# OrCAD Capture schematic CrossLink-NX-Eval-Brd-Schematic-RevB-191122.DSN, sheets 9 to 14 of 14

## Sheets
9 Configuration And ADC: size B; title: Configuration and ADC
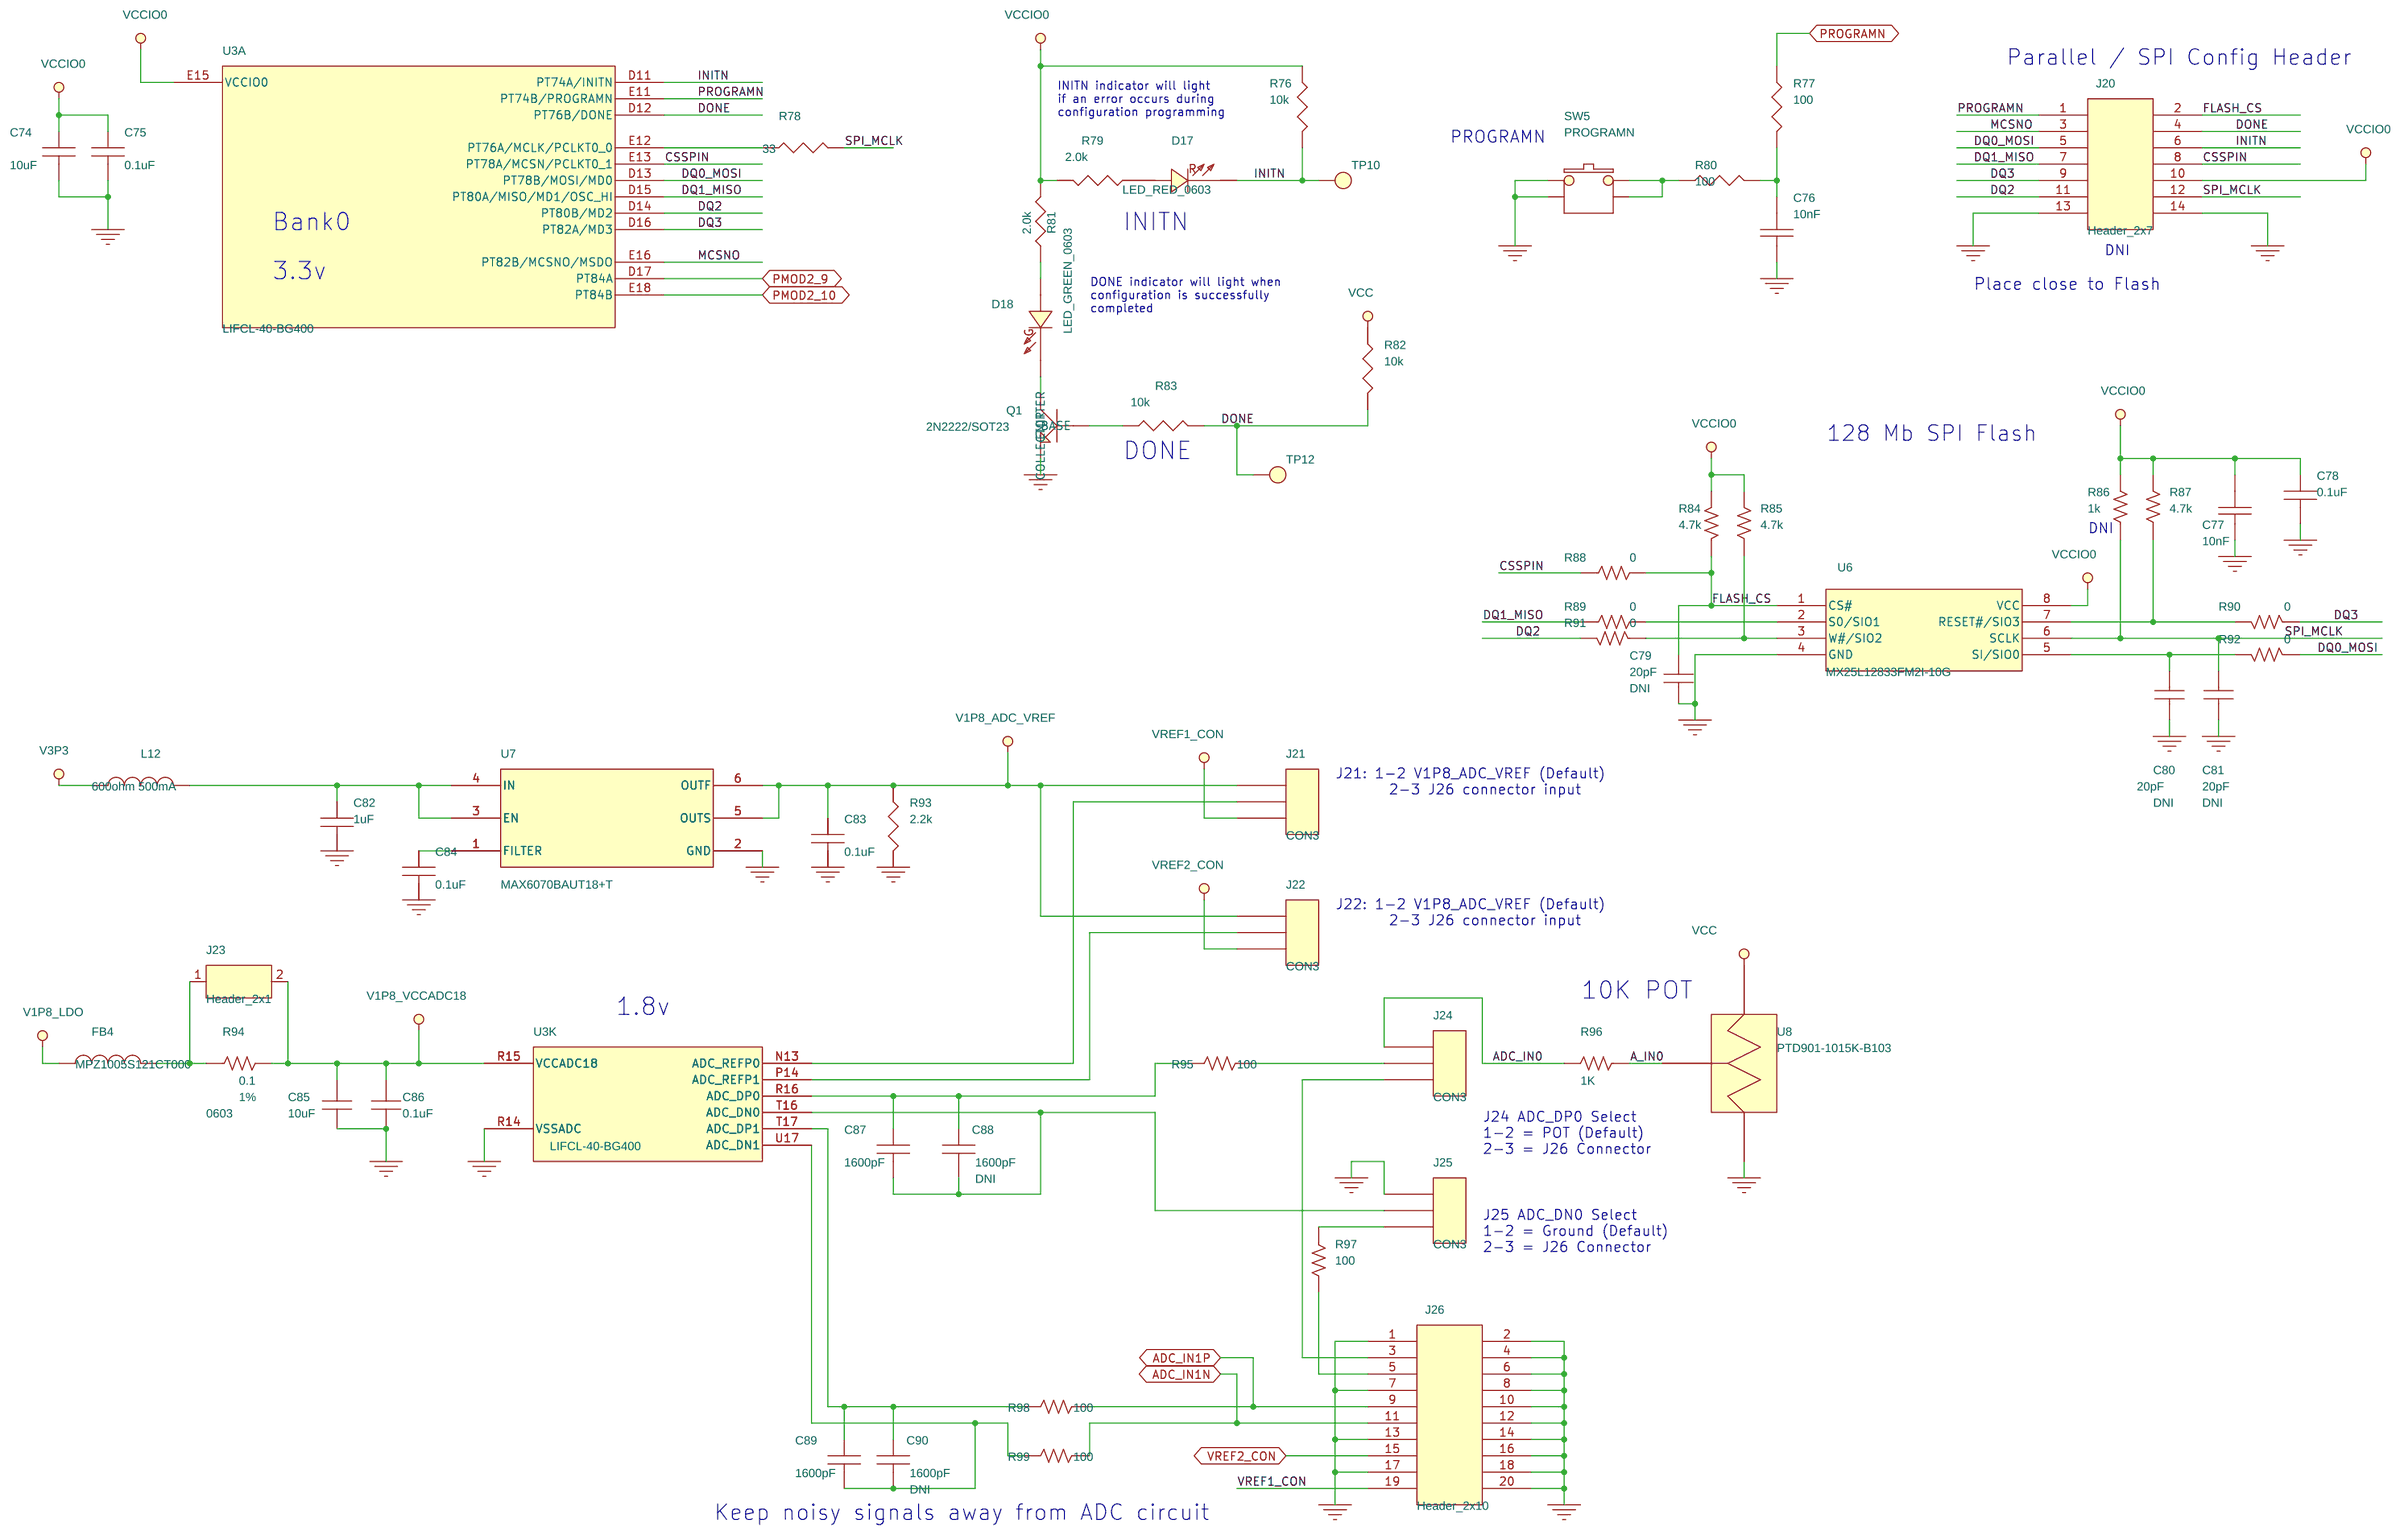
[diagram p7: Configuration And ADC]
10 FMC-LPC: size B; title: FMC-LPC
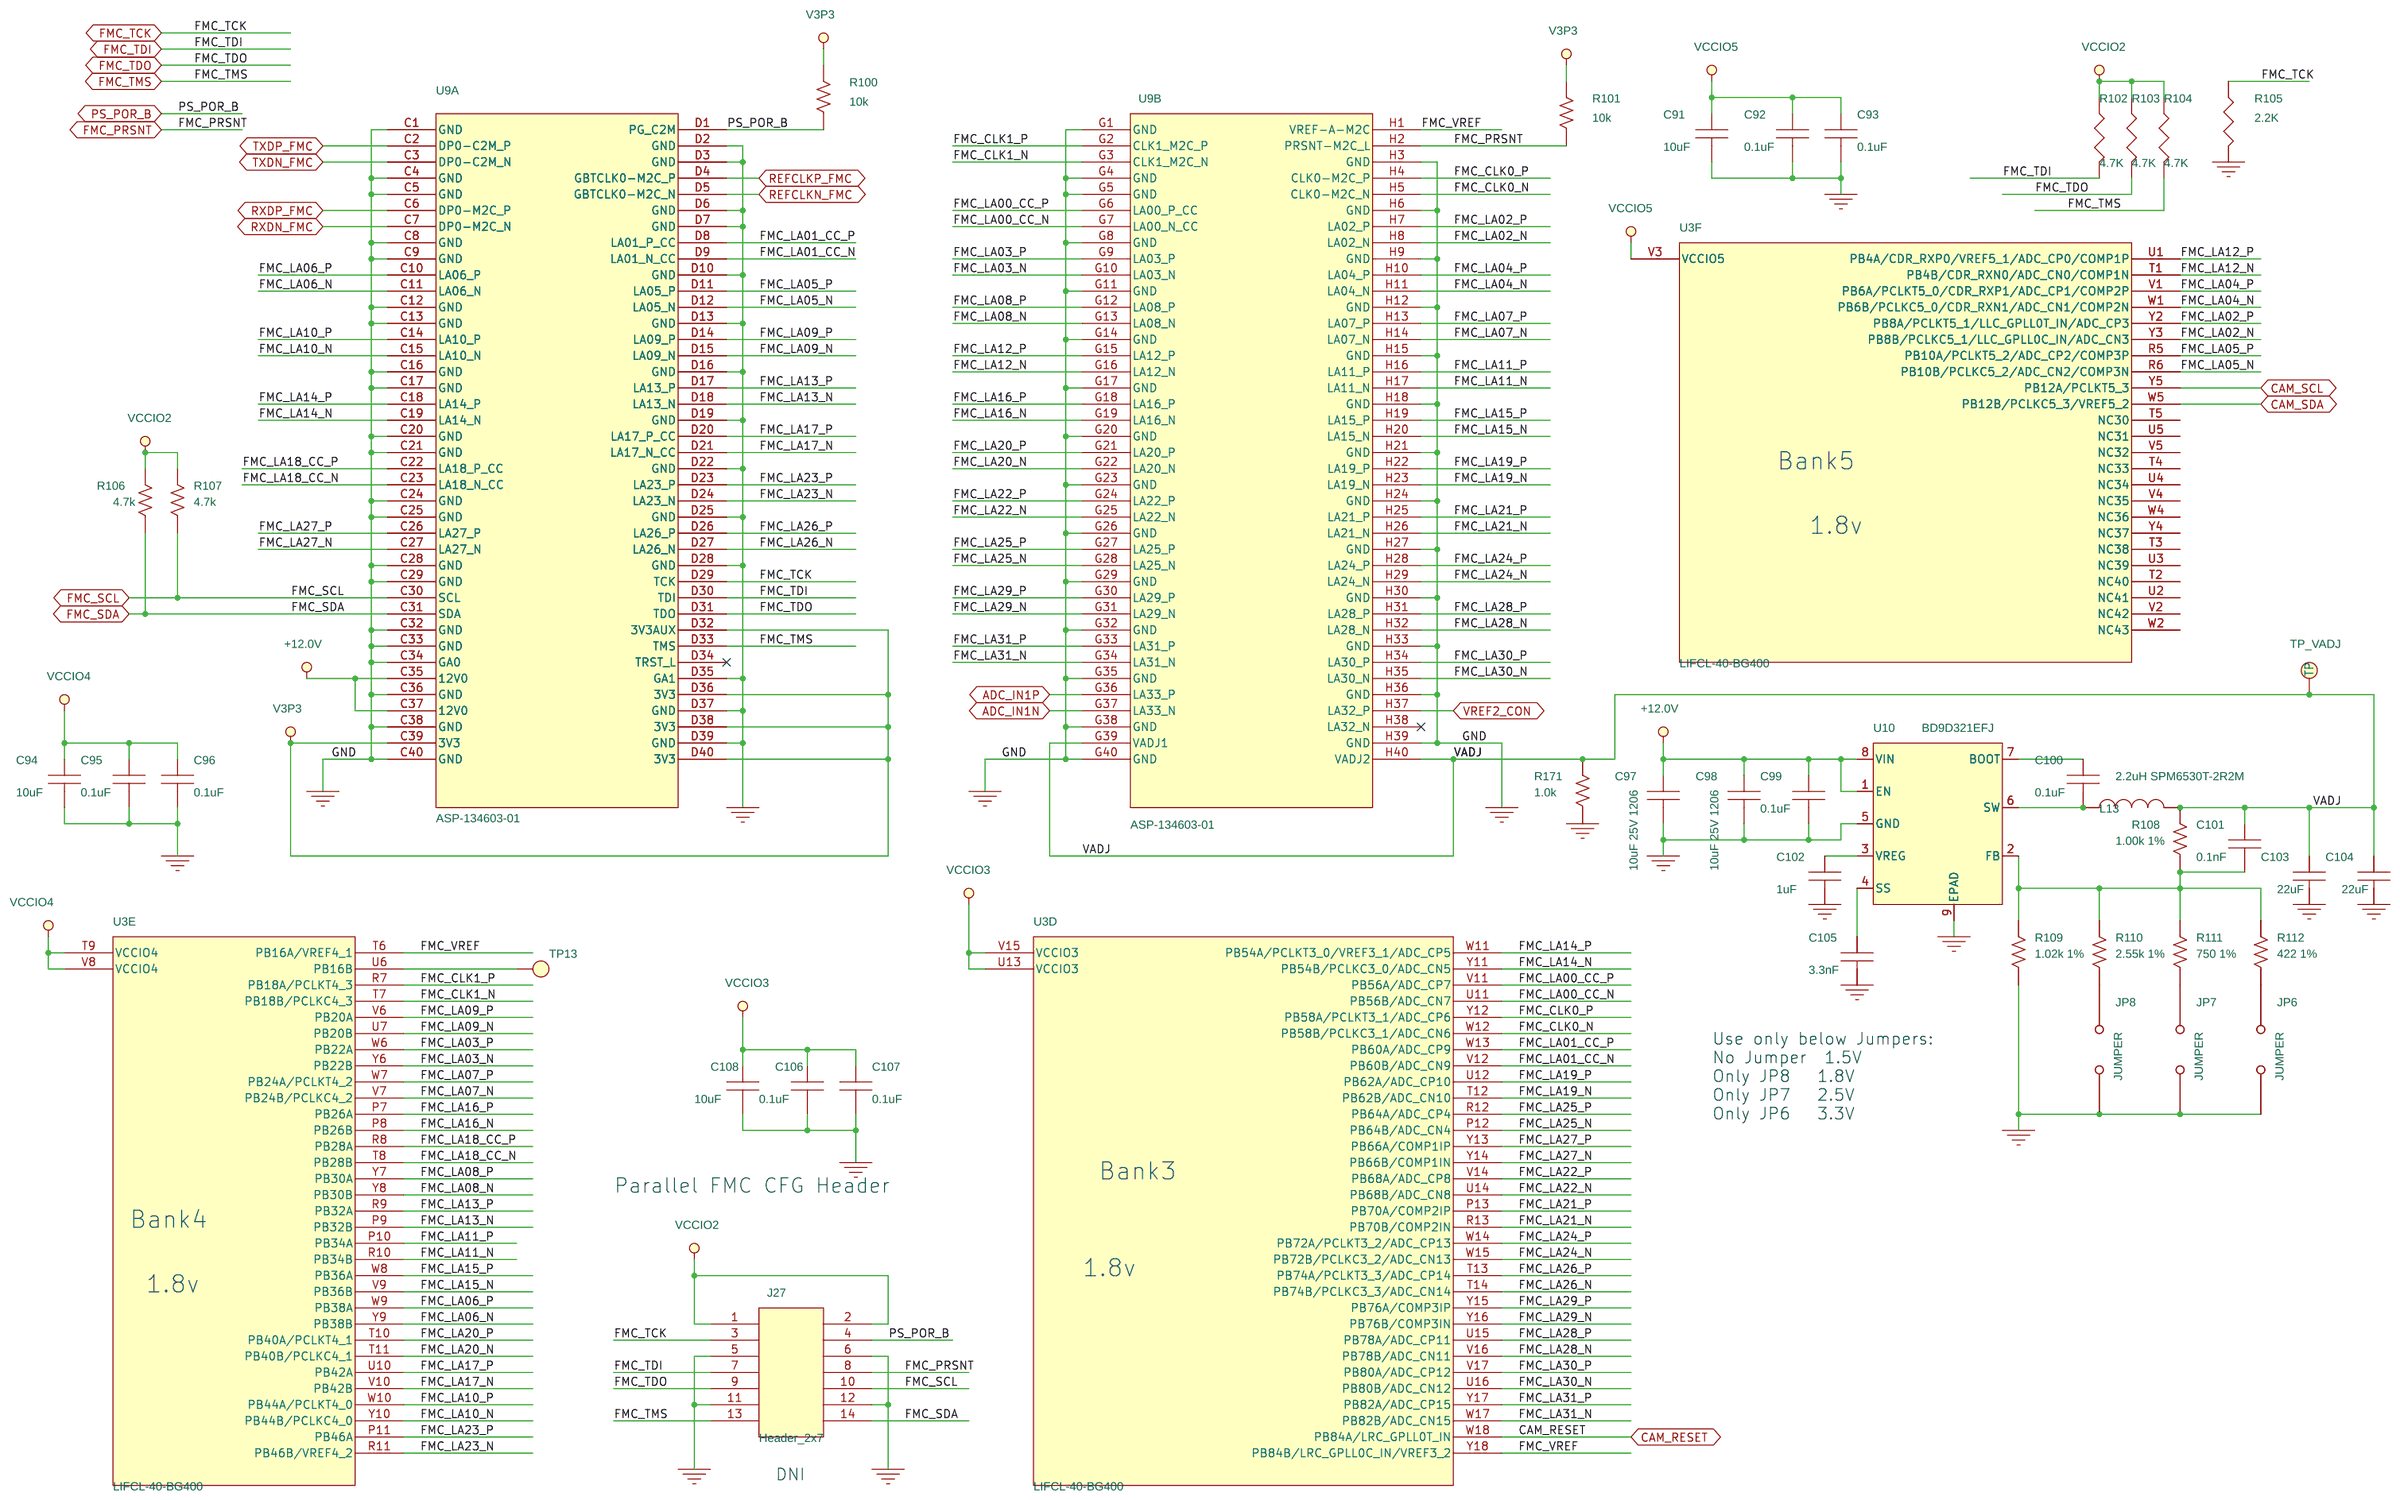
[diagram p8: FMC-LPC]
11 Power CSI and Bank Power: size B; title: Power CSI and Banks
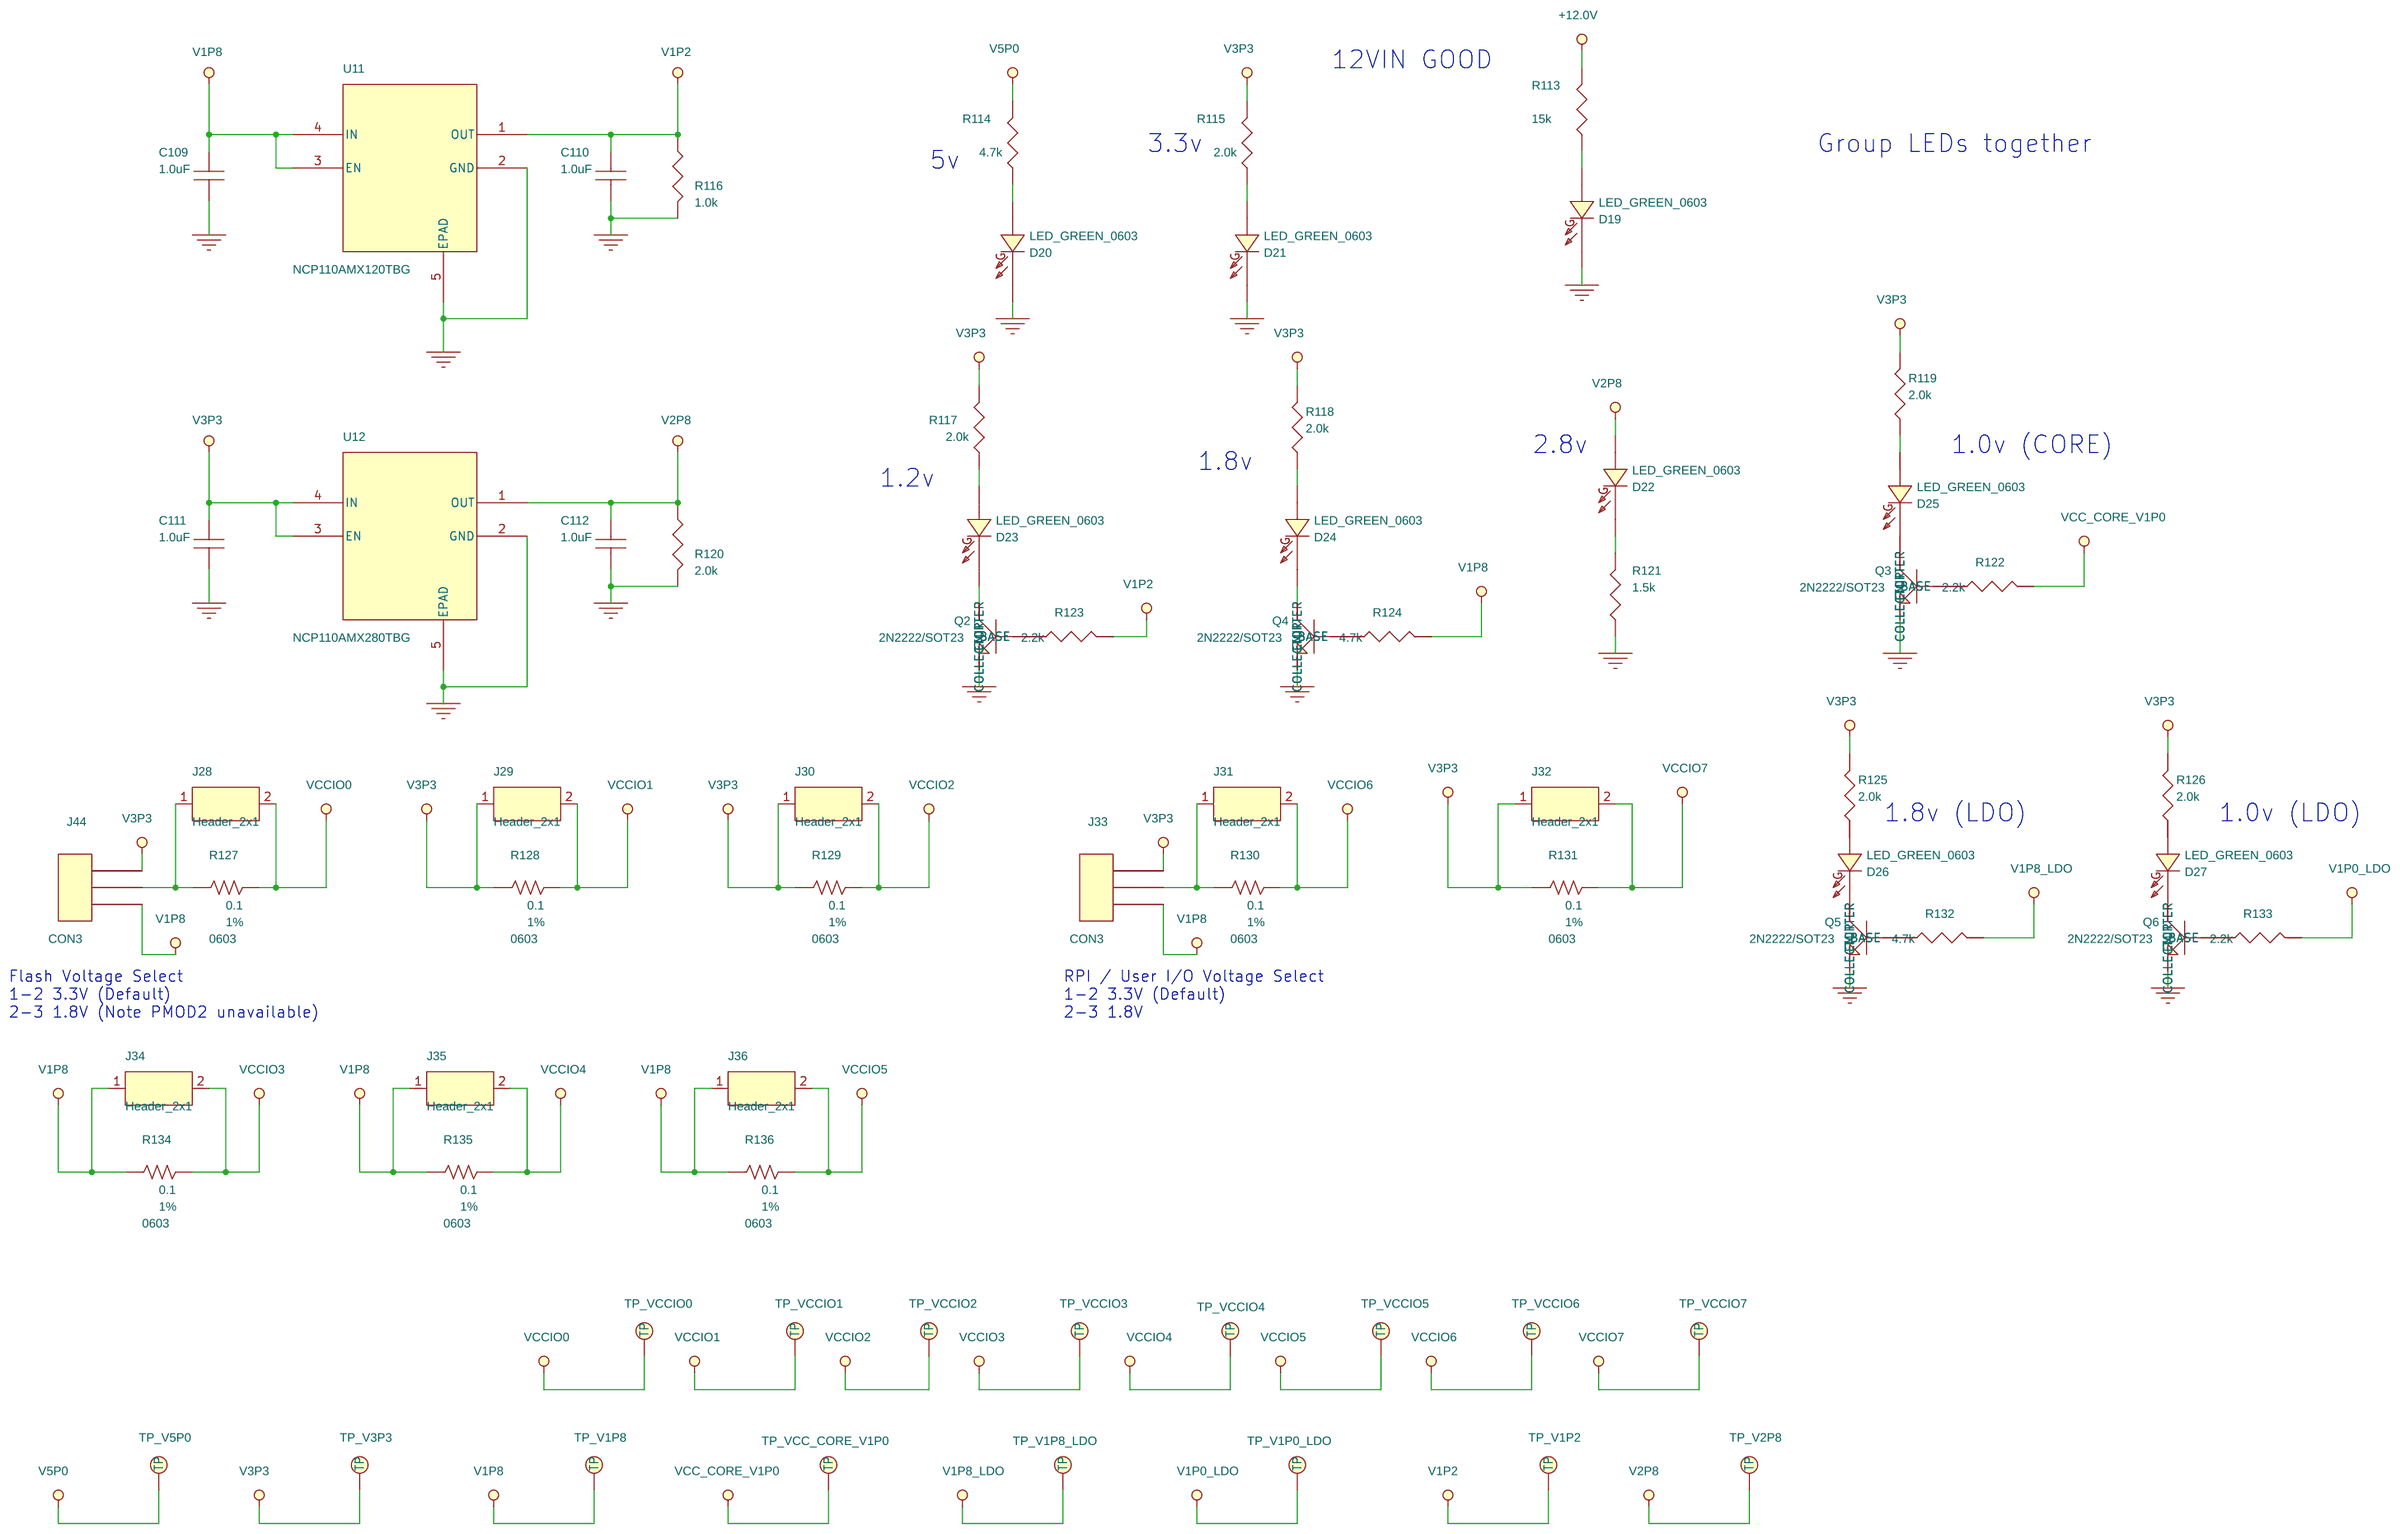
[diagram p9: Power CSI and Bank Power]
12 Power Decoupling: size B; title: Power Decoupling
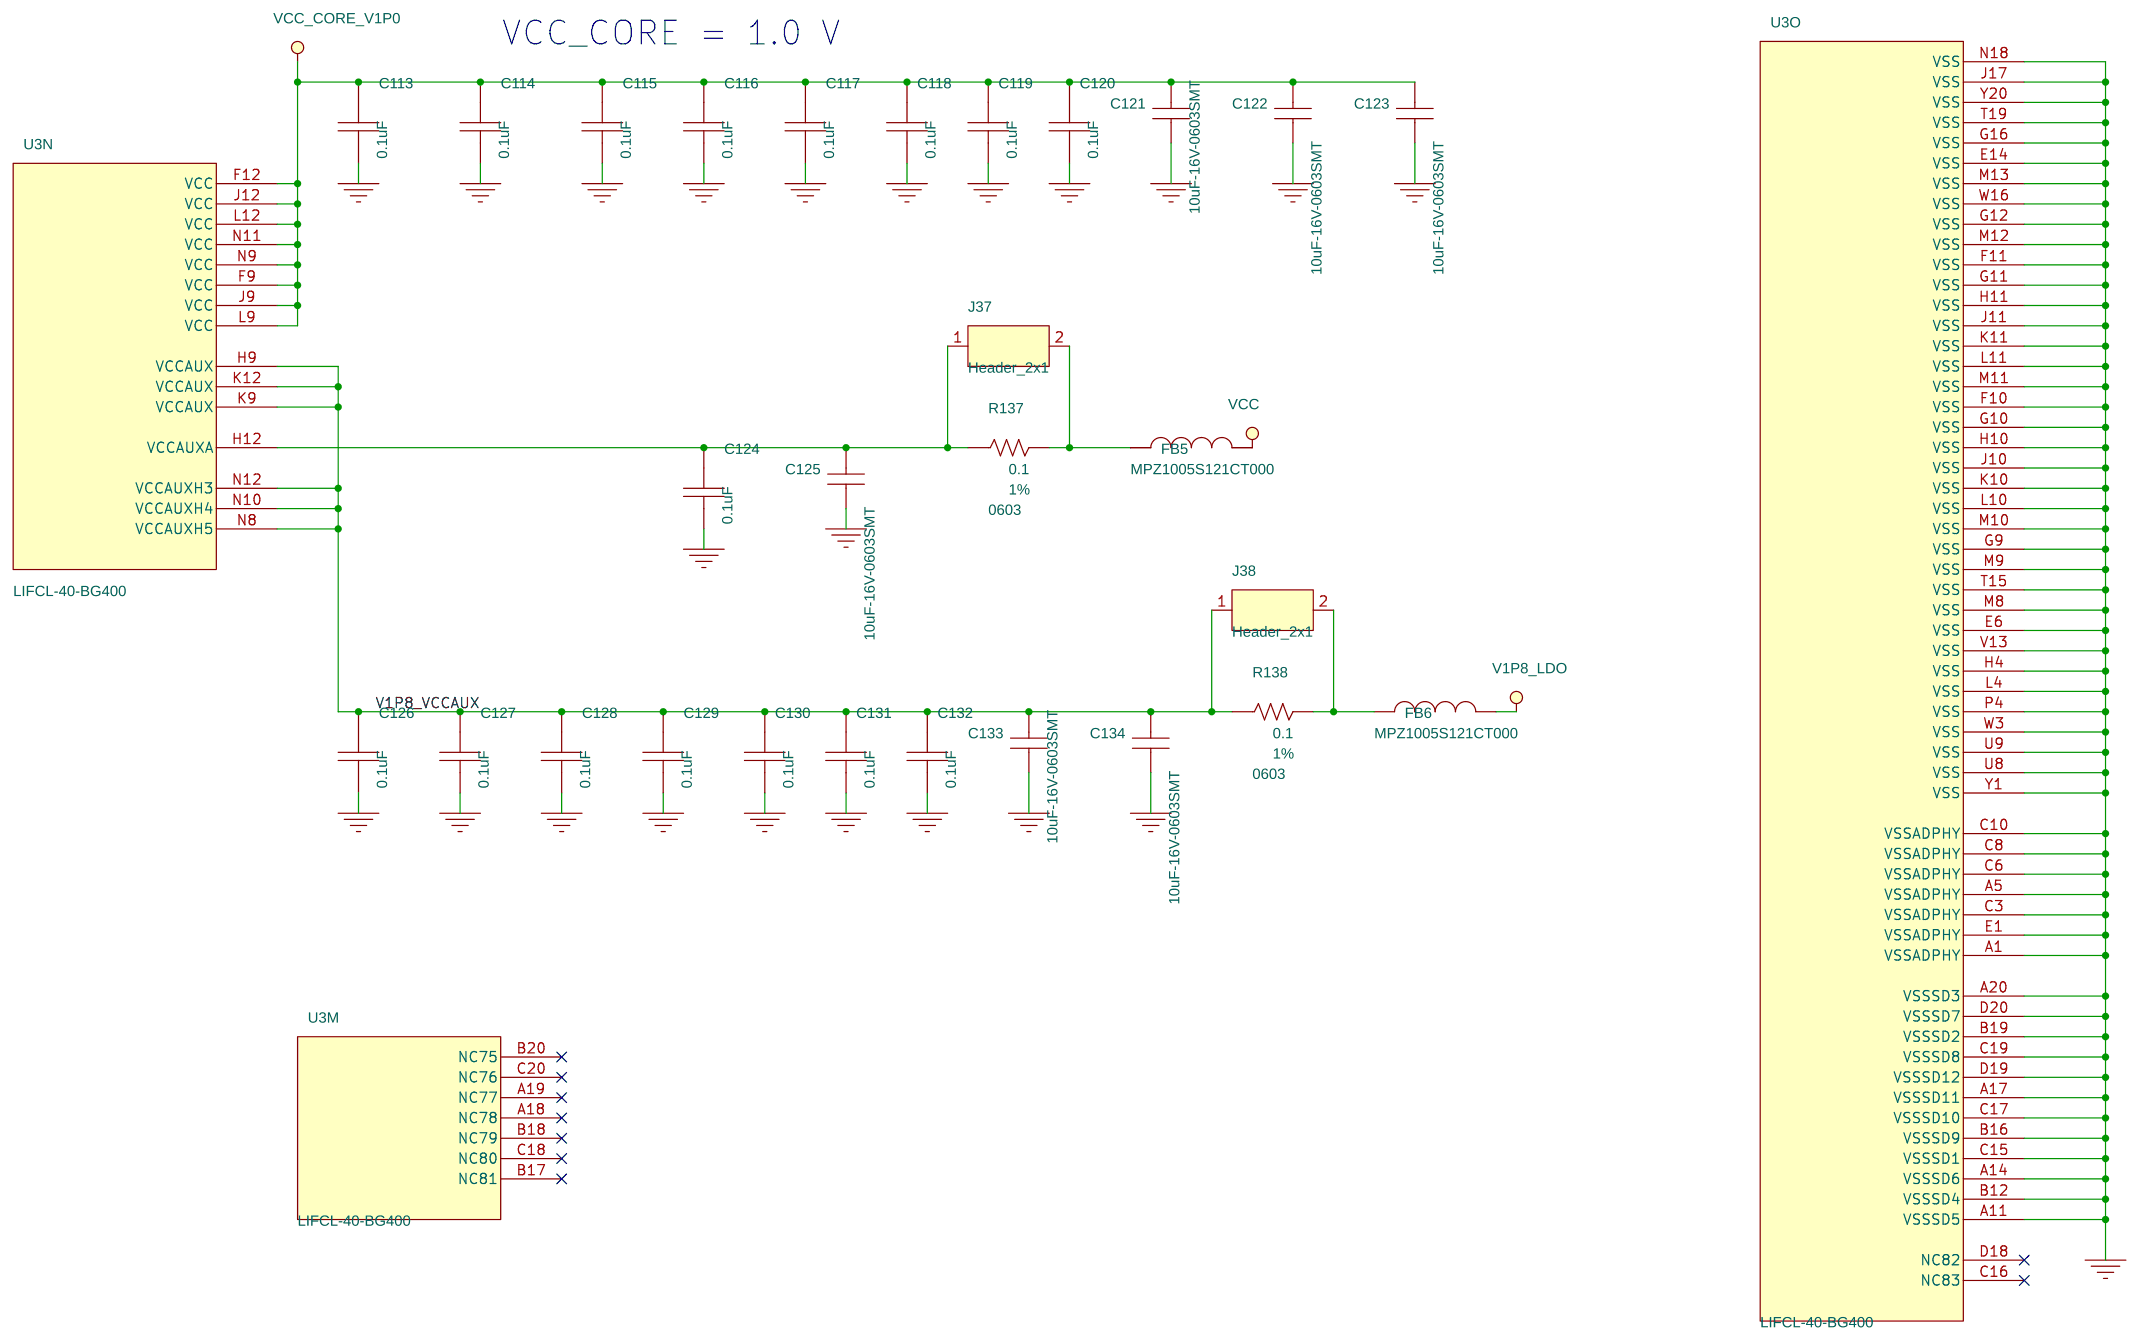
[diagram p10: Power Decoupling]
13 Power Regulators: size B; title: Power Regulators
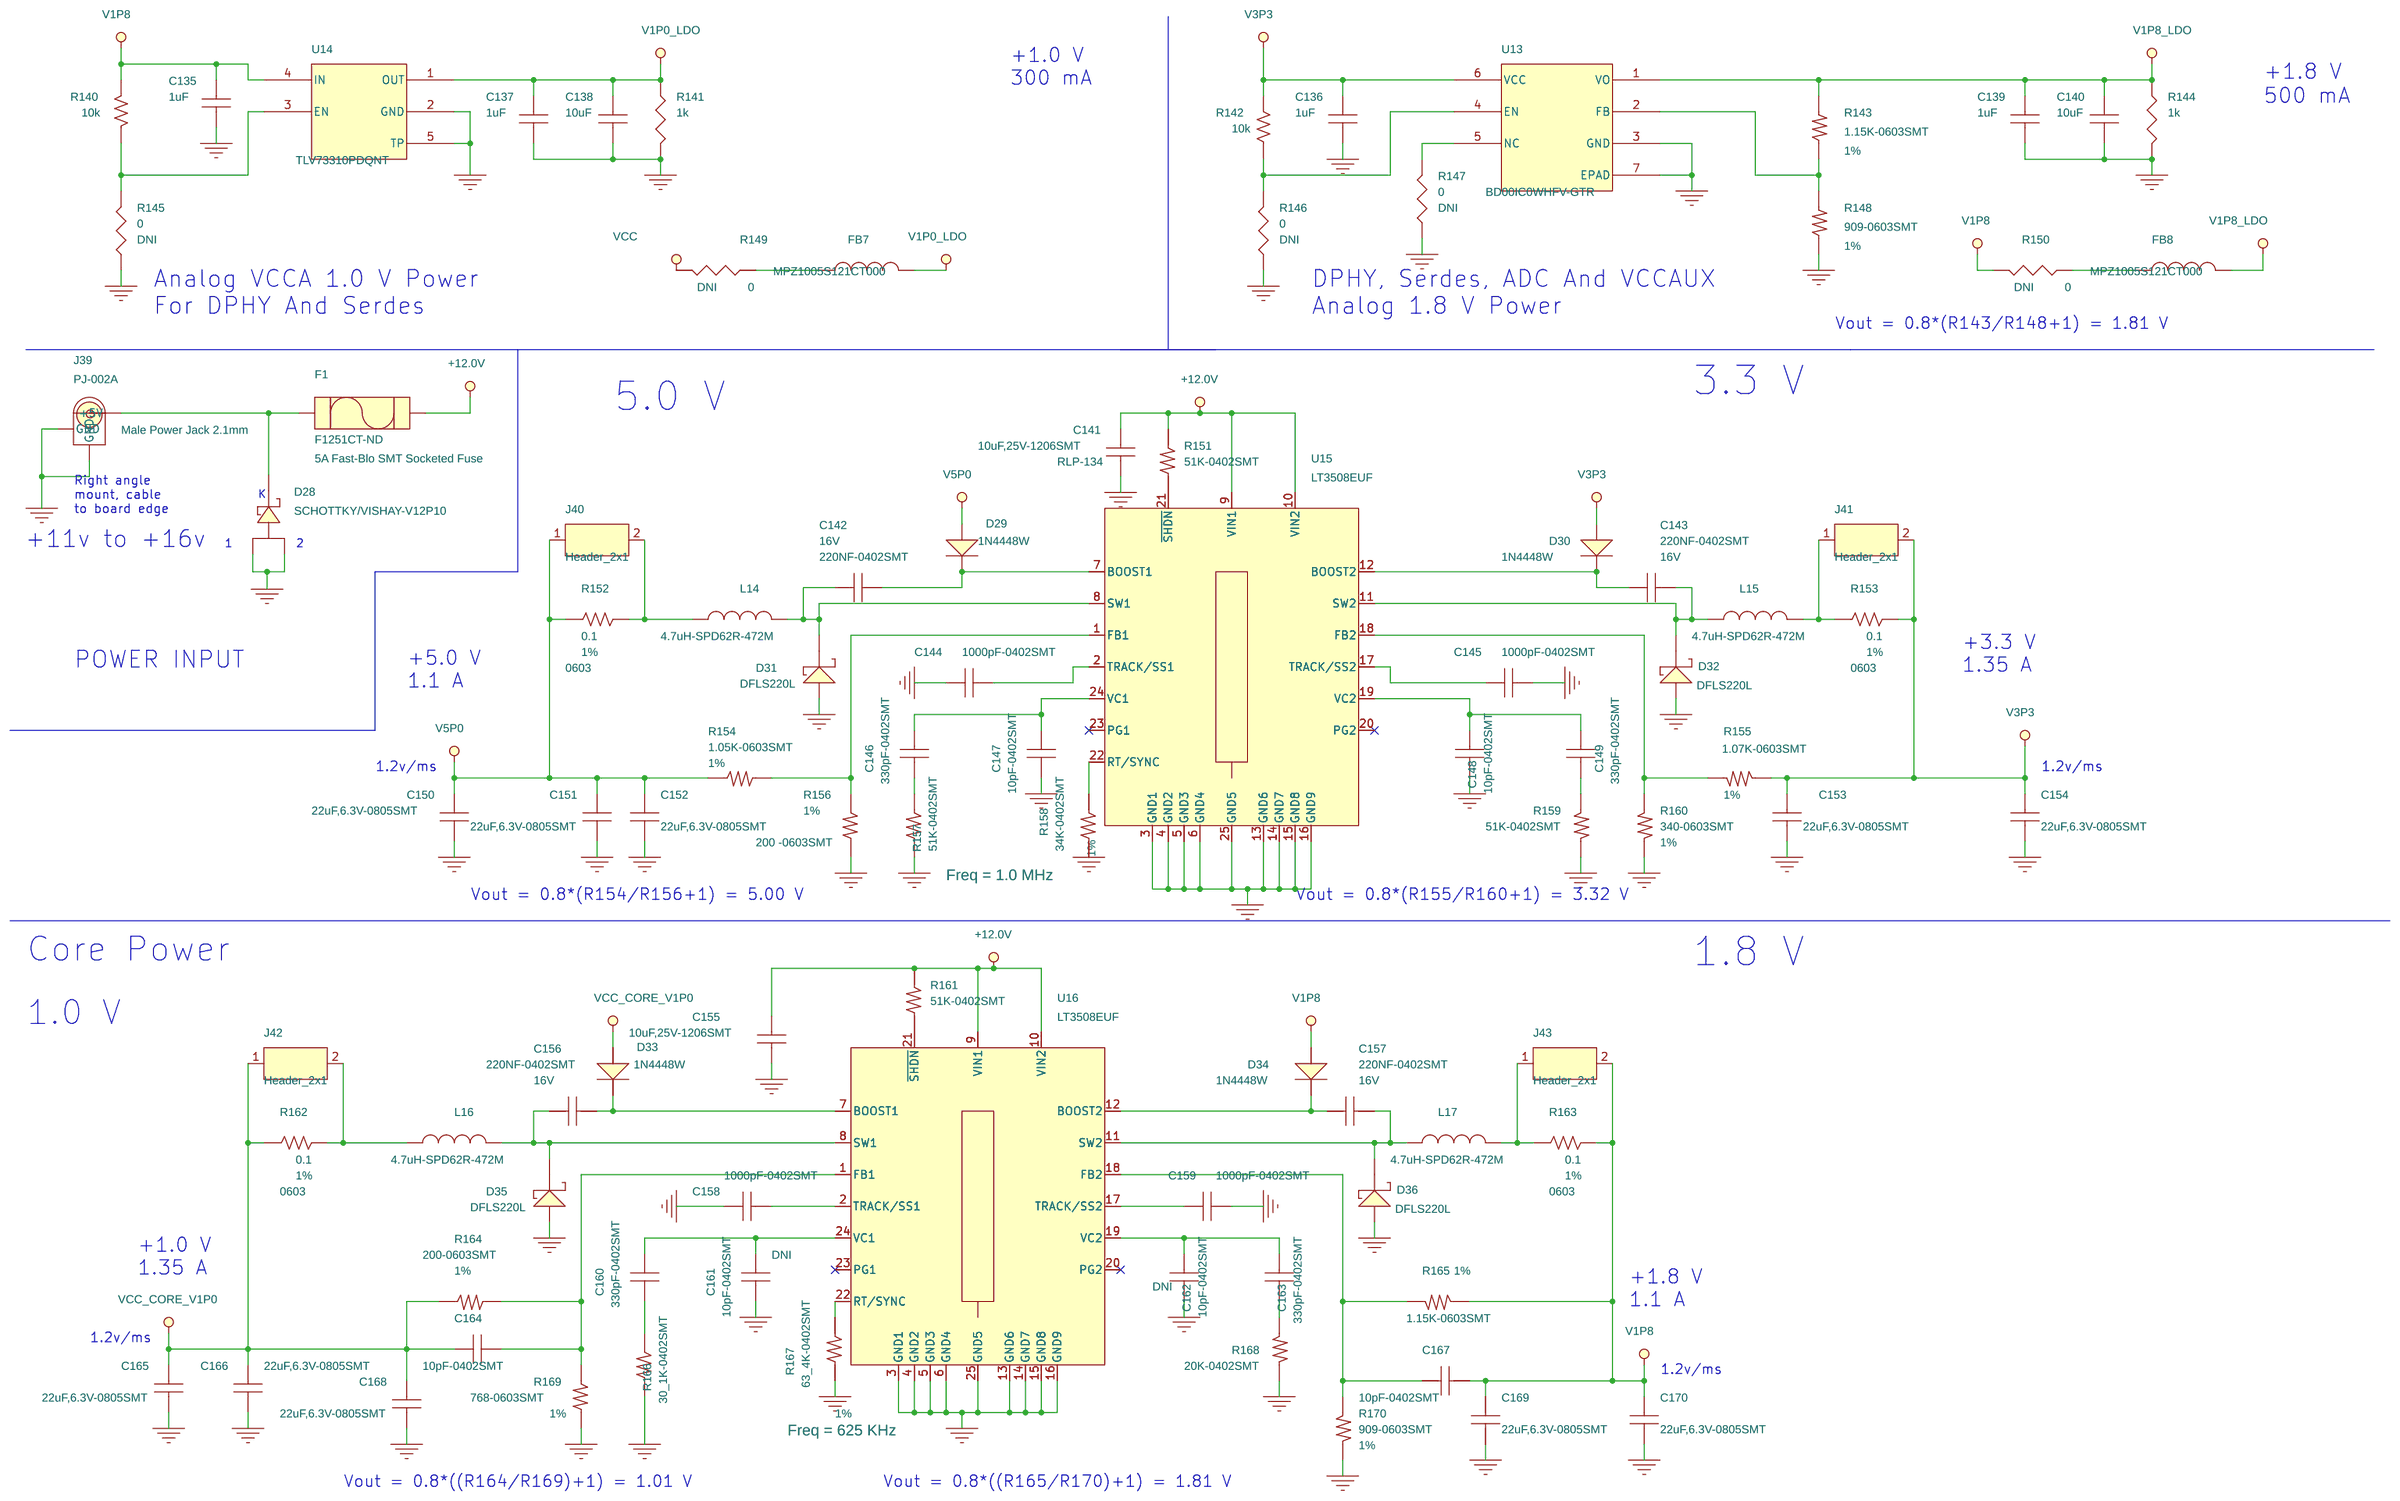
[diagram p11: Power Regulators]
14 Power Diagram: title: Power Block Diagram

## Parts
sheet Configuration And ADC
C74  10uF  [C0603]
C75  0.1uF  [C0201]
C76  10nF  [RLP-130-A]
C77  10nF  [RLP-130-A]
C78  0.1uF  [C0201]
C79  20pF  [RLP-132]
C80  20pF  [RLP-132]
C81  20pF  [RLP-132]
C82  1uF  [C0603]
C83  0.1uF  [C0201]
C84  0.1uF  [C0201]
C85  10uF  [C0402]
C86  0.1uF  [C0201]
C87  1600pF  [C0805]
C88  1600pF  [C0805]
C89  1600pF  [C0805]
C90  1600pF  [C0805]
D17  LED_RED_0603  [APT1608]
D18  LED_GREEN_0603  [APT1608]
FB4  MPZ1005S121CT000  [FB0402]
J20  Header_2x7  [Header_2x7]
J21  CON3  [CON3]
J22  CON3  [CON3]
J23  Header_2x1  [Header_2x1]
J24  CON3  [CON3]
J25  CON3  [CON3]
J26  Header_2x10  [Header_2x10]
L12  600ohm 500mA  [fb0603]
Q1  2N2222/SOT23  [MMBT2222ALT-1]
R76  10k  [R0402]
R77  100  [R0402]
R78  33  [R0402]
R79  2.0k  [R0402]
R80  100  [R0402]
R81  2.0k  [R0402]
R82  10k  [R0402]
R83  10k  [R0402]
R84  4.7k  [R0402]
R85  4.7k  [R0402]
R86  1k  [R0402]
R87  4.7k  [R0402]
R88  0  [R0402]
R89  0  [R0402]
R90  0  [R0402]
R91  0  [R0402]
R92  0  [R0402]
R93  2.2k  [R0402]
R94  0.1  [0603]
R95  100  [R0805]
R96  1K  [R0805]
R97  100  [R0805]
R98  100  [R0805]
R99  100  [R0805]
SW5  PROGRAMN  [4psmd_switch]
TP10  TestPoint  [TP50]
TP12  TestPoint  [TP50]
U6  MX25L12833FM2I-10G  [SO8_MX25L12833FM2I10G]
U7  MAX6070BAUT18+T  [SOT23-6_MAX6070]
U8  PTD901-1015K-B103  [PTD901_1015K_B103]
sheet FMC-LPC
C91  10uF  [C0603]
C92  0.1uF  [C0201]
C93  0.1uF  [C0201]
C94  10uF  [C0603]
C95  0.1uF  [C0201]
C96  0.1uF  [C0201]
C97  10uF 25V 1206  [C1206]
C98  10uF 25V 1206  [C1206]
C99  0.1uF  [C0201]
C100  0.1uF  [C0201]
C101  0.1nF  [C0603]
C102  1uF  [C0603]
C103  22uF  [C0603]
C104  22uF  [C0603]
C105  3.3nF  [C0201]
C106  0.1uF  [C0201]
C107  0.1uF  [C0201]
C108  10uF  [C0603]
J27  Header_2x7  [Header_2x7]
JP6  JUMPER  [Header_1x2]
JP7  JUMPER  [Header_1x2]
JP8  JUMPER  [Header_1x2]
L13  2.2uH SPM6530T-2R2M  [SPM6530T-2R2M]
R100  10k  [R0402]
R101  10k  [R0402]
R102  4.7K  [R0603]
R103  4.7K  [R0603]
R104  4.7K  [R0603]
R105  2.2K  [R0603]
R106  4.7k  [R0402]
R107  4.7k  [R0402]
R108  1.00k 1%  [R0402]
R109  1.02k 1%  [R0402]
R110  2.55k 1%  [R0402]
R111  750 1%  [R0402]
R112  422 1%  [R0402]
R171  1.0k  [R0402]
TP13  TestPoint  [TP50]
TP_VADJ  TP_S_40_63  [tp_s_40_63]
U9  ASP-134603-01  [ASP_134603_01]  (sections A,B)
U10  BD9D321EFJ  [HTSOP_8_BD9D321]
sheet Power CSI and Bank Power
C109  1.0uF  [C0603]
C110  1.0uF  [C0603]
C111  1.0uF  [C0603]
C112  1.0uF  [C0603]
D19  LED_GREEN_0603  [APT1608]
D20  LED_GREEN_0603  [APT1608]
D21  LED_GREEN_0603  [APT1608]
D22  LED_GREEN_0603  [APT1608]
D23  LED_GREEN_0603  [APT1608]
D24  LED_GREEN_0603  [APT1608]
D25  LED_GREEN_0603  [APT1608]
D26  LED_GREEN_0603  [APT1608]
D27  LED_GREEN_0603  [APT1608]
J28  Header_2x1  [Header_2x1]
J29  Header_2x1  [Header_2x1]
J30  Header_2x1  [Header_2x1]
J31  Header_2x1  [Header_2x1]
J32  Header_2x1  [Header_2x1]
J33  CON3  [CON3]
J34  Header_2x1  [Header_2x1]
J35  Header_2x1  [Header_2x1]
J36  Header_2x1  [Header_2x1]
J44  CON3  [CON3]
Q2  2N2222/SOT23  [MMBT2222ALT-1]
Q3  2N2222/SOT23  [MMBT2222ALT-1]
Q4  2N2222/SOT23  [MMBT2222ALT-1]
Q5  2N2222/SOT23  [MMBT2222ALT-1]
Q6  2N2222/SOT23  [MMBT2222ALT-1]
R113  15k  [RLP-103]
R114  4.7k  [R0402]
R115  2.0k  [R0402]
R116  1.0k  [R0402]
R117  2.0k  [R0402]
R118  2.0k  [R0402]
R119  2.0k  [R0402]
R120  2.0k  [R0402]
R121  1.5k  [R0402]
R122  2.2k  [R0402]
R123  2.2k  [R0402]
R124  4.7k  [R0402]
R125  2.0k  [R0402]
R126  2.0k  [R0402]
R127  0.1  [0603]
R128  0.1  [0603]
R129  0.1  [0603]
R130  0.1  [0603]
R131  0.1  [0603]
R132  4.7k  [R0402]
R133  2.2k  [R0402]
R134  0.1  [0603]
R135  0.1  [0603]
R136  0.1  [0603]
TP_V1P0_LDO  TP_S_40_63  [tp_s_40_63]
TP_V1P2  TP_S_40_63  [tp_s_40_63]
TP_V1P8  TP_S_40_63  [tp_s_40_63]
TP_V1P8_LDO  TP_S_40_63  [tp_s_40_63]
TP_V2P8  TP_S_40_63  [tp_s_40_63]
TP_V3P3  TP_S_40_63  [tp_s_40_63]
TP_V5P0  TP_S_40_63  [tp_s_40_63]
TP_VCC_CORE_V1P0  TP_S_40_63  [tp_s_40_63]
TP_VCCIO0  TP_S_40_63  [tp_s_40_63]
TP_VCCIO1  TP_S_40_63  [tp_s_40_63]
TP_VCCIO2  TP_S_40_63  [tp_s_40_63]
TP_VCCIO3  TP_S_40_63  [tp_s_40_63]
TP_VCCIO4  TP_S_40_63  [tp_s_40_63]
TP_VCCIO5  TP_S_40_63  [tp_s_40_63]
TP_VCCIO6  TP_S_40_63  [tp_s_40_63]
TP_VCCIO7  TP_S_40_63  [tp_s_40_63]
U11  NCP110AMX120TBG  [4XDFN_NCP110]
U12  NCP110AMX280TBG  [4XDFN_NCP110]
sheet Power Decoupling
C113  0.1uF  [C0201]
C114  0.1uF  [C0201]
C115  0.1uF  [C0201]
C116  0.1uF  [C0201]
C117  0.1uF  [C0201]
C118  0.1uF  [C0201]
C119  0.1uF  [C0201]
C120  0.1uF  [C0201]
C121  10uF-16V-0603SMT  [C0603]
C122  10uF-16V-0603SMT  [C0603]
C123  10uF-16V-0603SMT  [C0603]
C124  0.1uF  [C0201]
C125  10uF-16V-0603SMT  [C0603]
C126  0.1uF  [C0201]
C127  0.1uF  [C0201]
C128  0.1uF  [C0201]
C129  0.1uF  [C0201]
C130  0.1uF  [C0201]
C131  0.1uF  [C0201]
C132  0.1uF  [C0201]
C133  10uF-16V-0603SMT  [C0603]
C134  10uF-16V-0603SMT  [C0603]
FB5  MPZ1005S121CT000  [FB0402]
FB6  MPZ1005S121CT000  [FB0402]
J37  Header_2x1  [Header_2x1]
J38  Header_2x1  [Header_2x1]
R137  0.1  [0603]
R138  0.1  [0603]
sheet Power Regulators
C135  1uF  [C0603]
C136  1uF  [C0603]
C137  1uF  [C0603]
C138  10uF  [C0603]
C139  1uF  [C0603]
C140  10uF  [C0603]
C141  10uF,25V-1206SMT  [RLP-134]
C142  220NF-0402SMT  [RLP-130-A]
C143  220NF-0402SMT  [RLP-130-A]
C144  1000pF-0402SMT  [RLP-130-A]
C145  1000pF-0402SMT  [RLP-130-A]
C146  330pF-0402SMT  [RLP-130-A]
C147  10pF-0402SMT  [RLP-130-A]
C148  10pF-0402SMT  [RLP-130-A]
C149  330pF-0402SMT  [RLP-130-A]
C150  22uF,6.3V-0805SMT  [RLP-133]
C151  22uF,6.3V-0805SMT  [RLP-133]
C152  22uF,6.3V-0805SMT  [RLP-133]
C153  22uF,6.3V-0805SMT  [RLP-133]
C154  22uF,6.3V-0805SMT  [RLP-133]
C155  10uF,25V-1206SMT  [RLP-134]
C156  220NF-0402SMT  [RLP-130-A]
C157  220NF-0402SMT  [RLP-130-A]
C158  1000pF-0402SMT  [RLP-130-A]
C159  1000pF-0402SMT  [RLP-130-A]
C160  330pF-0402SMT  [RLP-130-A]
C161  10pF-0402SMT  [RLP-130-A]
C162  10pF-0402SMT  [RLP-130-A]
C163  330pF-0402SMT  [RLP-130-A]
C164  10pF-0402SMT  [RLP-130-A]
C165  22uF,6.3V-0805SMT  [RLP-133]
C166  22uF,6.3V-0805SMT  [RLP-133]
C167  10pF-0402SMT  [RLP-130-A]
C168  22uF,6.3V-0805SMT  [RLP-133]
C169  22uF,6.3V-0805SMT  [RLP-133]
C170  22uF,6.3V-0805SMT  [RLP-133]
D28  SCHOTTKY/VISHAY-V12P10  [V12P10]
D29  1N4448W  [1N4448W]
D30  1N4448W  [1N4448W]
D31  DFLS220L  [DFLS220L]
D32  DFLS220L  [DFLS220L]
D33  1N4448W  [1N4448W]
D34  1N4448W  [1N4448W]
D35  DFLS220L  [DFLS220L]
D36  DFLS220L  [DFLS220L]
F1  F1251CT-ND  [0154010]
FB7  MPZ1005S121CT000  [FB0402]
FB8  MPZ1005S121CT000  [FB0402]
J39  PJ-002A  [pj_002a_3p]
J40  Header_2x1  [Header_2x1]
J41  Header_2x1  [Header_2x1]
J42  Header_2x1  [Header_2x1]
J43  Header_2x1  [Header_2x1]
L14  4.7uH-SPD62R-472M  [SPD62R]
L15  4.7uH-SPD62R-472M  [SPD62R]
L16  4.7uH-SPD62R-472M  [SPD62R]
L17  4.7uH-SPD62R-472M  [SPD62R]
R140  10k  [R0402]
R141  1k  [R0402]
R142  10k  [R0402]
R143  1.15K-0603SMT  [RLP-101]
R144  1k  [R0402]
R145  0  [R0603]
R146  0  [R0603]
R147  0  [R0603]
R148  909-0603SMT  [RLP-101]
R149  0  [R0603]
R150  0  [R0603]
R151  51K-0402SMT  [RLP-100]
R152  0.1  [0603]
R153  0.1  [0603]
R154  1.05K-0603SMT  [RLP-101]
R155  1.07K-0603SMT  [RLP-101]
R156  200 -0603SMT  [RLP-101]
R157  51K-0402SMT  [RLP-100]
R158  34K-0402SMT  [RLP-100]
R159  51K-0402SMT  [RLP-100]
R160  340-0603SMT  [RLP-101]
R161  51K-0402SMT  [RLP-100]
R162  0.1  [0603]
R163  0.1  [0603]
R164  200-0603SMT  [RLP-101]
R165  1.15K-0603SMT  [RLP-101]
R166  30_1K-0402SMT  [RLP-100]
R167  63_4K-0402SMT  [RLP-100]
R168  20K-0402SMT  [RLP-100]
R169  768-0603SMT  [RLP-101]
R170  909-0603SMT  [RLP-101]
U13  BD00IC0WHFV-GTR  [6HVSOF_BD00IC0WHFV]
U14  TLV73310PDQNT  [4X2SON]
U15  LT3508EUF  [LT3508EUF]
U16  LT3508EUF  [LT3508EUF]
sheet Raspberry Pi
U3  LIFCL-40-BG400  [LIFCL-40-BG400]  (sections A,B,C,D,E,F,G,H,I,J,K,L,M,N,O)

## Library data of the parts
C74 C91 C94 C108 = 10uF_0603
C75 C78 C83 C84 C92 C93 C95 C96 C99 C100 C106 C107 = 0u1_0402: CAP CER 0.1UF 25V 10% X5R 0201; Manufacturer: Murata; Manufacturer Part Number: GRM033R61E104KE14J
C76 C77 = CAP_1
C79-C81 = CAP_NP: Assy: DNI; COMPFIXED: NO; COMPGROUP: 0; COMPHEIGHT: 0.000; COMPKEY: NO; COMPLOC: [1820.000,2015.000]; COMPLOCKED: NO; COMPROT: 270; COMPSIDE: TOP; DECOUPLER: NO; FPLIST: SM/C_0402; MEMORY: NO; populate: DNI
C82 = 4u7_0603: CAP CER 4.7UF 6.3V 10% X5R 0603; Digikey P/N: PCC2396CT-ND
C85 = CAP_CER_100nF_0402_10V: CAP CER 0.1UF 10V X7R 0402; MFG: Wurth; MFG P/N: 885012205018; Manufacturer: Wurth; Manufacturer Part Number: 885012205018
C86 = CAP_CER_100nF_0402_10V: CAP CER 0.1UF 25V 10% X5R 0201; Manufacturer: Murata; Manufacturer Part Number: GRM033R61E104KE14J
C87 C89 = 0u1_0402: CAP CER 1.6nF 50V 5% X5R 0201; Digikey P/N: 399-15458-1-ND; Manufacturer: Kemet; Manufacturer Part Number: C0805C162J5GAC7800
C88 C90 = 0u1_0402: CAP CER 1.6nF 50V 5% X5R 0201; Assy: DNI; Digikey P/N: 399-15458-1-ND; Manufacturer: Kemet; Manufacturer Part Number: C0805C162J5GAC7800
D17 = LED-SMT1206_RED_0
D18-D27 = LED-SMT1206_GREEN_1
FB4 FB7 FB8 = INDUCTOR_1: FERRITE BEAD 120 OHM 0402 1LN; Manufacturer: TDK Corporation
J20 = Header_2x7: Assy: DNL
J21 J22 J24 J25 J33 J44 = CON3: 3 Positions Header, Unshrouded Connector 0.100" (2.54mm) Through Hole Gold; Manufacturer: Wurth; PART_NUMBER: 61300311121
J23 J28-J32 J34-J38 J40-J43 = Header_2x1
J26 = Header_2x10
L12 = FB0603: FERRITE CHIP 600 OHM 500MA 0603
Q1-Q6 = 2N2222
R76 R82 = R: RES SMD 10K OHM 1% 1/16W 0402; MFG: Yageo; MFG P/N: RC0402FR-0710KL; Manufacturer: Yageo; Manufacturer Part Number: RC0402FR-0710KL
R77 = R: RES SMD 100 OHM 1% 1/16W 0402; MFG: Yageo; MFG P/N: RC0402FR-07100RL; Manufacturer: Yageo; Manufacturer Part Number: RC0402FR-07100RL
R78 = R: RES SMD 33 OHM 1% 1/10W 0402; Manufacturer: Panasonic; Manufacturer Part Number: ERJ-2RKF33R0X
R79 R81 R115 R117-R119 R125 R126 = RES_0: RES SMD 1K OHM 1% 1/10W 0402; Manufacturer: Panasonic; Manufacturer Part Number: ERJ-2RKF1001X
R80 = 0R_0603: RES SMD 100 OHM 1% 1/16W 0402; MFG: Yageo; MFG P/N: RC0402FR-07100RL; Manufacturer Part Number: RC0402FR-07100RL
R83 = RES_0: RES SMD 10K OHM 1% 1/16W 0402; MFG: Yageo; MFG P/N: RC0402FR-0710KL; Manufacturer: Yageo; Manufacturer Part Number: RC0402FR-0710KL
R84 R85 R87 R100 R101 R107-R112 R140 R142 R171 = R_v3: RES SMD 4.7K OHM 5% 1/10W 0402; COMPFIXED: NO; COMPGROUP: 0; COMPHEIGHT: 0.000; COMPKEY: NO; COMPLOC: [970.000,1160.000]; COMPLOCKED: NO; COMPROT: 180; COMPSIDE: TOP; DECOUPLER: NO; FPLIST: AX/RC05,SM/R_0603; MEMORY: NO; MFG: Panasonic; MFG P/N: ERJ-2GEJ472X; Manufacturer: Panasonic; Manufacturer Part Number: ERJ-2GEJ472X
R86 R106 = R_v3: RES SMD 1K OHM 1% 1/10W 0402; Assy: DNI; COMPFIXED: NO; COMPGROUP: 0; COMPHEIGHT: 0.000; COMPKEY: NO; COMPLOC: [970.000,1160.000]; COMPLOCKED: NO; COMPROT: 180; COMPSIDE: TOP; DECOUPLER: NO; FPLIST: AX/RC05,SM/R_0603; MEMORY: NO; Manufacturer: Panasonic; Manufacturer Part Number: ERJ-2RKF1001X
R88-R92 = R_v3: RES SMD 0.0OHM JUMPER 1/10W 0402; COMPFIXED: NO; COMPHEIGHT: 0.000; COMPKEY: NO; COMPLOC: [3325.000,1400.000]; COMPLOCKED: NO; COMPROT: 180; COMPSIDE: TOP; DECOUPLER: NO; FPLIST: AX/RC05; MEMORY: NO; Manufacturer: Panasonic; Manufacturer Part Number: ERJ-2GE0R00X
R93 R116 R120 R141 R144 = RES_1K_1W16_0402_5P: RES SMD 1K OHM 1% 1/10W 0402; Manufacturer: Panasonic; Manufacturer Part Number: ERJ-2RKF1001X
R94 R127-R131 R134-R138 R152 R153 R162 R163 = R_v3: COMPFIXED: NO; COMPGROUP: 0; COMPHEIGHT: 0.000; COMPKEY: NO; COMPLOC: [970.000,1160.000]; COMPLOCKED: NO; COMPROT: 180; COMPSIDE: TOP; DECOUPLER: NO; FPLIST: AX/RC05,SM/R_0603; MEMORY: NO; Tollerance: 1%
R95-R99 = R_v3: RES 1K OHM 1/10W 1% 0603 SMD; COMPFIXED: NO; COMPGROUP: 0; COMPHEIGHT: 0.000; COMPKEY: NO; COMPLOC: [2340.000,1470.000]; COMPLOCKED: NO; COMPROT: 0; COMPSIDE: BOT; DECOUPLER: NO; MEMORY: NO; Populate: DI
SW5 = SW_PUSHBUTTON-SPST_SM: SWITCH TACTILE SPST-NO 0.05A 12V; MFG: Wurth; MFG P/N: 434153017835; Man. Part #: 434153017835; Manufacturer: Wurth; Manufacturer Part Number: 434153017835
TP10 TP12 TP13 = T_POINT_R
U6 = N25QxxxA13xF8_0: IC FLASH 128MBIT 104MHZ 8SOP; Manufacturer: Macronix; Populate: DI
U7 = MAX6070BAUT18+T_0
U8 = PTD901-1015K-B103-ND
C97 C98 = 10uF_0603: CAP CER 10UF 25V X5R 1206; Manufacturer Part Number: TMK316BJ106KL-T
C101 = 10uF_0603: CAP CER 100PF 50V C0G/NPO 0603; Manufacturer: Yageo; Manufacturer Part Number: CC0603JRNPO9BN101
C102 = 10uF_0603: CAP CER 1UF 25V 10% X7R 0603; Manufacturer Part Number: TMK107B7105KA-T
C103 C104 = 10uF_0603: CAP CER 22UF 10V X5R 0603; Manufacturer: Murata; Manufacturer Part Number: GRM188R61A226ME15D
C105 = 0u1_0402: CAP CER 3300PF 25V X7R 0201; Manufacturer: Murata; Manufacturer Part Number: GRM033R71E332KA12D
J27 = Header_2x7
JP6-JP8 = JUMPER_0
L13 = INDUCTOR_0
R102-R104 = 5k1_0402: RES 4.70K OHM 1/10W 1% 0603 SMD; Digikey P/N: 541-4.70KHTR-ND; Manufacturer: Vishay; Manufacturer Part Number: CRCW06034K70FKEA
R105 = 5k1_0402: Digikey P/N: 541-2.20KHTR-ND; Manufacturer: Vishay; Manufacturer Part Number: CRCW06032K20FKEA
TP_V1P0_LDO TP_V1P2 TP_V1P8 TP_V1P8_LDO TP_V2P8 TP_V3P3 TP_V5P0 TP_VADJ TP_VCC_CORE_V1P0 TP_VCCIO0-TP_VCCIO7 = TP_S_40_63: Assy: DNI
U9 = ASP-134603-01: Color: Default; Location X-Coordinate: 0; Location Y-Coordinate: 0; Power Pins Visible: False; Primitive: DEFAULT; SPLIT_INST: TRUE; SWAP_INFO: (S1+S2)
U10 = BD9D321EFJ
C109-C112 C135-C140 = CAP_NP: CAP CER 10UF 10V 20% X6S 0603; MFG: Samsung; MFG P/N: CL10X106MP8NRNC; Man. Part #: CL10X106MP8NRNC; Manufacturer: Samsung; Manufacturer Part Number: CL10X106MP8NRNC
R113 = RES_0
R114 = RES_0: RES SMD 2.2K OHM 1% 1/10W 0402; Manufacturer: Panasonic; Manufacturer Part Number: ERJ-2RKF2201X
R121 = RES_0: RES SMD 750 OHM 5% 1/10W 0402; Manufacturer: Panasonic; Manufacturer Part Number: ERJ-2GEJ751X
R122-R124 R132 R133 = RES_0: RES SMD 4.7K OHM 5% 1/10W 0402; MFG: Panasonic; MFG P/N: ERJ-2GEJ472X; Manufacturer: Panasonic; Manufacturer Part Number: ERJ-2GEJ472X
U11 = NCP110AMX120TBG
U12 = NCP110AMX280TBG
C113-C117 C124 C126-C129 = CAP_1: CAP CER 0.1UF 25V 10% X5R 0201; Manufacturer: Murata; Manufacturer Part Number: GRM033R61E104KE14J
C118-C120 C130-C132 = CAP_SMT_0805: CAP CER 0.1UF 25V 10% X5R 0201; Manufacturer: Murata; Manufacturer Part Number: GRM033R61E104KE14J
C121-C123 C125 C133 C134 = CAP_NP: COMPFIXED: NO; COMPGROUP: 0; COMPHEIGHT: 0.000; COMPKEY: NO; COMPLOC: [1820.000,2015.000]; COMPLOCKED: NO; COMPROT: 270; COMPSIDE: TOP; DECOUPLER: NO; FPLIST: SM/C_0402; MEMORY: NO
FB5 FB6 = INDUCTOR_0: FERRITE BEAD 120 OHM 0402 1LN; Manufacturer: TDK Corporation
C141 C144-C149 C155 C158-C160 C163 C164 C167 = CAP-NP
C142 C143 C156 C157 = CAP-NP: COMPFIXED: 16V
C150-C154 C165 C166 C168-C170 = CAP-NP: CAP CER 22UF 10V X5R 0805; Manufacturer: Samsung; Manufacturer Part Number: CL21A226KPCLRNC
C161 C162 = CAP-NP: ASSY: DNI; Populate: DNI
D28 = DIODE_SCHOTTKY21
D29 D30 D33 D34 = DIODE_0
D31 D32 D35 D36 = D-SCHOTTKY_0
F1 = SMTFUSE_0: 5A Fast-Blo SMT Socketed Fuse
J39 = 22HP037A: Male Power Jack 2.1mm
L14 L16 = IND: COMPFIXED: SUMIDA; COMPGROUP: CDRH3D18
L15 L17 = IND: COMPFIXED: SUMIDA; COMPGROUP: CDRH3D18C
R143 R148 R154-R157 R159 R160 R164-R166 R168-R170 = R_v2: COMPFIXED: 1%
R145-R147 R149 R150 = 0R_0603: RES 0.0 OHM 1/10W JUMP 0603 SMD; Assy: DNI
R151 R161 = R_v2
R158 = R_v2: COMPFIXED: 1%; COMPGROUP: Freq = 1.0 MHz
R167 = R_v2: COMPFIXED: 1%; COMPGROUP: Freq = 625 KHz
U13 = BD00IC0WHFV-GTR
U14 = TLV73310PDQNT
U15 U16 = LT3508EUF-QFN24UF-4X4_0
U3 = LIFCL-40-BG400: Color: Default; Location X-Coordinate: 0; Location Y-Coordinate: 0; Power Pins Visible: False; Primitive: DEFAULT; SPLIT_INST: TRUE; SWAP_INFO: (S1+S2+S3+S4+S5+S6+S7+S8+S9+S10+S11+S12+S13+S14+S15)

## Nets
+12.0V: C97.1 C98.1 C99.1 C141.1 C155.1 F1.2 R113.2 R151.1 R161.1 U9.C35(12V0) U9.C37(12V0) U10.1(EN) U10.8(VIN) U15.9(VIN1) U15.10(VIN2) U16.9(VIN1) U16.10(VIN2)
GND: C74.2 C75.2 C76.2 C77.2 C78.2 C79.2 C80.2 C81.2 C82.2 C83.2 C84.2 C85.1 C86.1 C91.2 C92.2 C93.2 C94.2 C95.2 C96.2 C97.2 C98.2 C99.2 C102.2 C103.2 C104.2 C105.2 C106.2 C107.2 C108.2 C109.2 C110.2 C111.2 C112.2 C113.2 C114.2 C115.2 C116.2 C117.2 C118.2 C119.2 C120.2 C121.1 C122.1 C123.1 C124.2 C125.1 C126.2 C127.2 C128.2 C129.2 C130.2 C131.2 C132.2 C133.1 C134.1 C135.2 C136.2 C137.2 C138.2 C139.2 C140.2 C141.2 C144.1 C145.2 C147.2 C148.2 C150.2 C151.2 C152.2 C153.2 C154.2 C155.2 C158.1 C159.2 C161.2 C162.2 C165.2 C166.2 C168.2 C169.2 C170.2 D19.1(CATHODE) D20.1(CATHODE) D21.1(CATHODE) D28.1(Anode1) D28.2(Anode2) D31.2 D32.2 D35.2 D36.2 J20.13 J20.14 J25.1 J26.1 J26.2 J26.4 J26.6 J26.7 J26.8 J26.10 J26.12 J26.13 J26.14 J26.16 J26.17 J26.18 J26.20 J27.5 J27.6 J27.11 J27.12 J39.2(GND) J39.3(GND) JP6.2 JP7.2 JP8.2 Q1.2(EMITTER) Q2.2(EMITTER) Q3.2(EMITTER) Q4.2(EMITTER) Q5.2(EMITTER) Q6.2(EMITTER) R93.2 R105.2 R109.1 R116.2 R120.2 R121.1 R141.2 R144.2 R145.2 R146.2 R147.2 R148.1 R156.2 R157.2 R158.2 R159.2 R160.2 R166.2 R167.2 R168.2 R169.2 R170.2 R171.1 SW5.2 SW5.4 U3.A1(VSSADPHY) U3.A5(VSSADPHY) U3.A11(VSSSD5) U3.A14(VSSSD6) U3.A17(VSSSD11) U3.A20(VSSSD3) U3.B12(VSSSD4) U3.B16(VSSSD9) U3.B19(VSSSD2) U3.C3(VSSADPHY) U3.C6(VSSADPHY) U3.C8(VSSADPHY) U3.C10(VSSADPHY) U3.C15(VSSSD1) U3.C17(VSSSD10) U3.C19(VSSSD8) U3.D19(VSSSD12) U3.D20(VSSSD7) U3.E1(VSSADPHY) U3.E6(VSS) U3.E14(VSS) U3.F10(VSS) U3.F11(VSS) U3.G9(VSS) U3.G10(VSS) U3.G11(VSS) U3.G12(VSS) U3.G16(VSS) U3.H4(VSS) U3.H10(VSS) U3.H11(VSS) U3.J10(VSS) U3.J11(VSS) U3.J17(VSS) U3.K10(VSS) U3.K11(VSS) U3.L4(VSS) U3.L10(VSS) U3.L11(VSS) U3.M8(VSS) U3.M9(VSS) U3.M10(VSS) U3.M11(VSS) U3.M12(VSS) U3.M13(VSS) U3.N18(VSS) U3.P4(VSS) U3.R14(VSSADC) U3.T15(VSS) U3.T19(VSS) U3.U8(VSS) U3.U9(VSS) U3.V13(VSS) U3.W3(VSS) U3.W16(VSS) U3.Y1(VSS) U3.Y20(VSS) U6.4(GND) U7.2(GND) U8.1 U9.C1(GND) U9.C4(GND) U9.C5(GND) U9.C8(GND) U9.C9(GND) U9.C12(GND) U9.C13(GND) U9.C16(GND) U9.C17(GND) U9.C20(GND) U9.C21(GND) U9.C24(GND) U9.C25(GND) U9.C28(GND) U9.C29(GND) U9.C32(GND) U9.C33(GND) U9.C34(GA0) U9.C36(GND) U9.C38(GND) U9.C40(GND) U9.D2(GND) U9.D3(GND) U9.D6(GND) U9.D7(GND) U9.D10(GND) U9.D13(GND) U9.D16(GND) U9.D19(GND) U9.D22(GND) U9.D25(GND) U9.D28(GND) U9.D35(GA1) U9.D37(GND) U9.D39(GND) U9.G1(GND) U9.G4(GND) U9.G5(GND) U9.G8(GND) U9.G11(GND) U9.G14(GND) U9.G17(GND) U9.G20(GND) U9.G23(GND) U9.G26(GND) U9.G29(GND) U9.G32(GND) U9.G35(GND) U9.G38(GND) U9.G40(GND) U9.H3(GND) U9.H6(GND) U9.H9(GND) U9.H12(GND) U9.H15(GND) U9.H18(GND) U9.H21(GND) U9.H24(GND) U9.H27(GND) U9.H30(GND) U9.H33(GND) U9.H36(GND) U9.H39(GND) U10.5(GND) U10.9(EPAD) U11.2(GND) U11.5(EPAD) U12.2(GND) U12.5(EPAD) U13.3(GND) U13.7(EPAD) U14.2(GND) U14.5(TP) U15.3(GND1) U15.4(GND2) U15.5(GND3) U15.6(GND4) U15.13(GND6) U15.14(GND7) U15.15(GND8) U15.16(GND9) U15.25(GND5) U16.3(GND1) U16.4(GND2) U16.5(GND3) U16.6(GND4) U16.13(GND6) U16.14(GND7) U16.15(GND8) U16.16(GND9) U16.25(GND5) ; also on sheet 3 4 5 6 7 8
V1P0_LDO: C137.1 C138.1 FB7.2 R133.2 R141.1 TP_V1P0_LDO.1(TP) U14.1(OUT) ; also on sheet 4 6
V1P2: C110.1 R116.1 R123.2 TP_V1P2.1(TP) U11.1(OUT) ; also on sheet 4
V1P8: C109.1 C135.1 C167.2 C169.1 C170.1 D34.2 J33.3 J34.1 J35.1 J36.1 J43.2 J44.3 R124.2 R134.1 R135.1 R136.1 R140.2 R150.2 R163.2 R165.1 TP_V1P8.1(TP) U11.3(EN) U11.4(IN) U14.4(IN) ; also on sheet 4 5
V1P8_ADC_VREF: C83.1 J21.1 J22.1 R93.1 U7.5(OUTS) U7.6(OUTF)
V1P8_LDO: C139.1 C140.1 FB4.2 FB5.2 FB6.2 FB8.2 R132.2 R143.2 R144.1 TP_V1P8_LDO.1(TP) U13.1(VO) ; also on sheet 4 6
V1P8_VCCADC18: C85.2 C86.2 J23.2 R94.2 U3.R15(VCCADC18) U8.3
V1P8_VCCAUX: C126.1 C127.1 C128.1 C129.1 C130.1 C131.1 C132.1 C133.2 C134.2 J38.1 R138.1 U3.H9(VCCAUX) U3.K9(VCCAUX) U3.K12(VCCAUX) U3.N8(VCCAUXH5) U3.N10(VCCAUXH4) U3.N12(VCCAUXH3)
V2P8: C112.1 D22.2(ANODE) R120.1 TP_V2P8.1(TP) U12.1(OUT) ; also on sheet 4
V3P3: C111.1 C136.1 C153.1 C154.1 D30.2 J29.1 J30.1 J32.1 J33.1 J41.2 J44.1 L12.2 R100.2 R101.2 R115.2 R117.2 R118.2 R119.2 R125.2 R126.2 R128.1 R129.1 R131.1 R142.2 R153.2 R155.1 TP_V3P3.1(TP) U9.C39(3V3) U9.D32(3V3AUX) U9.D36(3V3) U9.D38(3V3) U9.D40(3V3) U12.3(EN) U12.4(IN) U13.6(VCC) ; also on sheet 3 5 6
V5P0: C150.1 C151.1 C152.1 D29.2 J40.1 R114.2 R152.1 R154.1 TP_V5P0.1(TP) ; also on sheet 5
VCC_CORE_V1P0: C113.1 C114.1 C115.1 C116.1 C117.1 C118.1 C119.1 C120.1 C121.2 C122.2 C123.2 C164.1 C165.1 C166.1 C168.1 D33.2 J42.1 R122.2 R149.2 R162.1 R164.1 TP_VCC_CORE_V1P0.1(TP) U3.F9(VCC) U3.F12(VCC) U3.J9(VCC) U3.J12(VCC) U3.L9(VCC) U3.L12(VCC) U3.N9(VCC) U3.N11(VCC)
VCCIO0: C74.1 C75.1 C77.1 C78.1 J20.10 J28.2 R76.1 R79.2 R81.2 R82.1 R84.2 R85.2 R86.2 R87.2 R127.2 TP_VCCIO0.1(TP) U3.E15(VCCIO0) U6.8(VCC) ; also on sheet 3
VCCIO1: J29.2 R128.2 TP_VCCIO1.1(TP) ; also on sheet 3 7
VCCIO2: J27.1 J27.2 J30.2 R102.1 R103.1 R104.1 R106.2 R107.2 R129.2 TP_VCCIO2.1(TP) ; also on sheet 6 7
VCCIO3: C106.1 C107.1 C108.1 J34.2 R134.2 TP_VCCIO3.1(TP) U3.U13(VCCIO3) U3.V15(VCCIO3)
VCCIO4: C94.1 C95.1 C96.1 J35.2 R135.2 TP_VCCIO4.1(TP) U3.T9(VCCIO4) U3.V8(VCCIO4)
VCCIO5: C91.1 C92.1 C93.1 J36.2 R136.2 TP_VCCIO5.1(TP) U3.V3(VCCIO5) ; also on sheet 4
VCCIO6: J31.2 R130.2 TP_VCCIO6.1(TP) ; also on sheet 5
VCCIO7: J32.2 R131.2 TP_VCCIO7.1(TP) ; also on sheet 8
A_IN0: R96.1 U8.2
ADC_IN0: J24.1 R96.2
ADC_IN1N: J26.11 R99.1 U9.G37(LA33_N)
ADC_IN1P: J26.9 R98.1 U9.G36(LA33_P)
CAM_RESET: U3.W18(PB84A/LRC_GPLL0T_IN) ; also on sheet 4
CAM_SCL: U3.Y5(PB12A/PCLKT5_3) ; also on sheet 4
CAM_SDA: U3.W5(PB12B/PCLKC5_3/VREF5_2) ; also on sheet 4
CSSPIN: J20.8 R88.1 U3.E13(PT78A/MCSN/PCLKT0_1)
DONE: J20.4 R82.2 R83.2 TP12.1(TP) U3.D12(PT76B/DONE)
DQ0_MOSI: J20.5 R92.1 U3.D13(PT78B/MOSI/MD0)
DQ1_MISO: J20.7 R89.1 U3.D15(PT80A/MISO/MD1/OSC_HI)
DQ2: J20.11 R91.2 U3.D14(PT80B/MD2)
DQ3: J20.9 R90.1 U3.D16(PT82A/MD3)
FLASH_CS: C79.1 J20.2 R84.1 R88.2 U6.1(CS#)
FMC_CLK0_N: U3.W12(PB58B/PCLKC3_1/ADC_CN6) U9.H5(CLK0-M2C_N)
FMC_CLK0_P: U3.Y12(PB58A/PCLKT3_1/ADC_CP6) U9.H4(CLK0-M2C_P)
FMC_CLK1_N: U3.T7(PB18B/PCLKC4_3) U9.G3(CLK1_M2C_N)
FMC_CLK1_P: U3.R7(PB18A/PCLKT4_3) U9.G2(CLK1_M2C_P)
FMC_LA00_CC_N: U3.U11(PB56B/ADC_CN7) U9.G7(LA00_N_CC)
FMC_LA00_CC_P: U3.V11(PB56A/ADC_CP7) U9.G6(LA00_P_CC)
FMC_LA01_CC_N: U3.V12(PB60B/ADC_CN9) U9.D9(LA01_N_CC)
FMC_LA01_CC_P: U3.W13(PB60A/ADC_CP9) U9.D8(LA01_P_CC)
FMC_LA02_N: U3.Y3(PB8B/PCLKC5_1/LLC_GPLL0C_IN/ADC_CN3) U9.H8(LA02_N)
FMC_LA02_P: U3.Y2(PB8A/PCLKT5_1/LLC_GPLL0T_IN/ADC_CP3) U9.H7(LA02_P)
FMC_LA03_N: U3.Y6(PB22B) U9.G10(LA03_N)
FMC_LA03_P: U3.W6(PB22A) U9.G9(LA03_P)
FMC_LA04_N: U3.W1(PB6B/PCLKC5_0/CDR_RXN1/ADC_CN1/COMP2N) U9.H11(LA04_N)
FMC_LA04_P: U3.V1(PB6A/PCLKT5_0/CDR_RXP1/ADC_CP1/COMP2P) U9.H10(LA04_P)
FMC_LA05_N: U3.R6(PB10B/PCLKC5_2/ADC_CN2/COMP3N) U9.D12(LA05_N)
FMC_LA05_P: U3.R5(PB10A/PCLKT5_2/ADC_CP2/COMP3P) U9.D11(LA05_P)
FMC_LA06_N: U3.Y9(PB38B) U9.C11(LA06_N)
FMC_LA06_P: U3.W9(PB38A) U9.C10(LA06_P)
FMC_LA07_N: U3.V7(PB24B/PCLKC4_2) U9.H14(LA07_N)
FMC_LA07_P: U3.W7(PB24A/PCLKT4_2) U9.H13(LA07_P)
FMC_LA08_N: U3.Y8(PB30B) U9.G13(LA08_N)
FMC_LA08_P: U3.Y7(PB30A) U9.G12(LA08_P)
FMC_LA09_N: U3.U7(PB20B) U9.D15(LA09_N)
FMC_LA09_P: U3.V6(PB20A) U9.D14(LA09_P)
FMC_LA10_N: U3.Y10(PB44B/PCLKC4_0) U9.C15(LA10_N)
FMC_LA10_P: U3.W10(PB44A/PCLKT4_0) U9.C14(LA10_P)
FMC_LA11_N: U3.R10(PB34B) U9.H17(LA11_N)
FMC_LA11_P: U3.P10(PB34A) U9.H16(LA11_P)
FMC_LA12_N: U3.T1(PB4B/CDR_RXN0/ADC_CN0/COMP1N) U9.G16(LA12_N)
FMC_LA12_P: U3.U1(PB4A/CDR_RXP0/VREF5_1/ADC_CP0/COMP1P) U9.G15(LA12_P)
FMC_LA13_N: U3.P9(PB32B) U9.D18(LA13_N)
FMC_LA13_P: U3.R9(PB32A) U9.D17(LA13_P)
FMC_LA14_N: U3.Y11(PB54B/PCLKC3_0/ADC_CN5) U9.C19(LA14_N)
FMC_LA14_P: U3.W11(PB54A/PCLKT3_0/VREF3_1/ADC_CP5) U9.C18(LA14_P)
FMC_LA15_N: U3.V9(PB36B) U9.H20(LA15_N)
FMC_LA15_P: U3.W8(PB36A) U9.H19(LA15_P)
FMC_LA16_N: U3.P8(PB26B) U9.G19(LA16_N)
FMC_LA16_P: U3.P7(PB26A) U9.G18(LA16_P)
FMC_LA17_N: U3.V10(PB42B) U9.D21(LA17_N_CC)
FMC_LA17_P: U3.U10(PB42A) U9.D20(LA17_P_CC)
FMC_LA18_CC_N: U3.T8(PB28B) U9.C23(LA18_N_CC)
FMC_LA18_CC_P: U3.R8(PB28A) U9.C22(LA18_P_CC)
FMC_LA19_N: U3.T12(PB62B/ADC_CN10) U9.H23(LA19_N)
FMC_LA19_P: U3.U12(PB62A/ADC_CP10) U9.H22(LA19_P)
FMC_LA20_N: U3.T11(PB40B/PCLKC4_1) U9.G22(LA20_N)
FMC_LA20_P: U3.T10(PB40A/PCLKT4_1) U9.G21(LA20_P)
FMC_LA21_N: U3.R13(PB70B/COMP2IN) U9.H26(LA21_N)
FMC_LA21_P: U3.P13(PB70A/COMP2IP) U9.H25(LA21_P)
FMC_LA22_N: U3.U14(PB68B/ADC_CN8) U9.G25(LA22_N)
FMC_LA22_P: U3.V14(PB68A/ADC_CP8) U9.G24(LA22_P)
FMC_LA23_N: U3.R11(PB46B/VREF4_2) U9.D24(LA23_N)
FMC_LA23_P: U3.P11(PB46A) U9.D23(LA23_P)
FMC_LA24_N: U3.W15(PB72B/PCLKC3_2/ADC_CN13) U9.H29(LA24_N)
FMC_LA24_P: U3.W14(PB72A/PCLKT3_2/ADC_CP13) U9.H28(LA24_P)
FMC_LA25_N: U3.P12(PB64B/ADC_CN4) U9.G28(LA25_N)
FMC_LA25_P: U3.R12(PB64A/ADC_CP4) U9.G27(LA25_P)
FMC_LA26_N: U3.T14(PB74B/PCLKC3_3/ADC_CN14) U9.D27(LA26_N)
FMC_LA26_P: U3.T13(PB74A/PCLKT3_3/ADC_CP14) U9.D26(LA26_P)
FMC_LA27_N: U3.Y14(PB66B/COMP1IN) U9.C27(LA27_N)
FMC_LA27_P: U3.Y13(PB66A/COMP1IP) U9.C26(LA27_P)
FMC_LA28_N: U3.V16(PB78B/ADC_CN11) U9.H32(LA28_N)
FMC_LA28_P: U3.U15(PB78A/ADC_CP11) U9.H31(LA28_P)
FMC_LA29_N: U3.Y16(PB76B/COMP3IN) U9.G31(LA29_N)
FMC_LA29_P: U3.Y15(PB76A/COMP3IP) U9.G30(LA29_P)
FMC_LA30_N: U3.U16(PB80B/ADC_CN12) U9.H35(LA30_N)
FMC_LA30_P: U3.V17(PB80A/ADC_CP12) U9.H34(LA30_P)
FMC_LA31_N: U3.W17(PB82B/ADC_CN15) U9.G34(LA31_N)
FMC_LA31_P: U3.Y17(PB82A/ADC_CP15) U9.G33(LA31_P)
FMC_PRSNT: J27.8 R101.1 U9.H2(PRSNT-M2C_L) ; also on sheet 6
FMC_SCL: J27.10 R107.1 U9.C30(SCL) ; also on sheet 6
FMC_SDA: J27.14 R106.1 U9.C31(SDA) ; also on sheet 6
FMC_TCK: J27.3 R105.1 U9.D29(TCK) ; also on sheet 6
FMC_TDI: J27.7 R102.2 U9.D30(TDI) ; also on sheet 6
FMC_TDO: J27.9 R103.2 U9.D31(TDO) ; also on sheet 6
FMC_TMS: J27.13 R104.2 U9.D33(TMS) ; also on sheet 6
FMC_VREF: U3.T6(PB16A/VREF4_1) U3.Y18(PB84B/LRC_GPLL0C_IN/VREF3_2) U9.H1(VREF-A-M2C)
INITN: D17.1(CATHODE) J20.6 R76.2 TP10.1(TP) U3.D11(PT74A/INITN)
MCSNO: J20.3 U3.E16(PT82B/MCSNO/MSDO)
PMOD2_9: U3.D17(PT84A) ; also on sheet 8
PMOD2_10: U3.E18(PT84B) ; also on sheet 8
PROGRAMN: J20.1 R77.1 U3.E11(PT74B/PROGRAMN) ; also on sheet 3
PS_POR_B: J27.4 R100.1 U9.D1(PG_C2M) ; also on sheet 6
REFCLKN_FMC: U9.D5(GBTCLK0-M2C_N) ; also on sheet 6
REFCLKP_FMC: U9.D4(GBTCLK0-M2C_P) ; also on sheet 6
RXDN_FMC: U9.C7(DP0-M2C_N) ; also on sheet 6
RXDP_FMC: U9.C6(DP0-M2C_P) ; also on sheet 6
SPI_MCLK: C81.1 J20.12 R78.1 R86.1 U6.6(SCLK)
TXDN_FMC: U9.C3(DP0-C2M_N) ; also on sheet 6
TXDP_FMC: U9.C2(DP0-C2M_P) ; also on sheet 6
VADJ: C101.1 C103.1 C104.1 L13.2 R108.2 R171.2 TP_VADJ.1(TP) U9.G39(VADJ1) U9.H40(VADJ2)
VREF1_CON: J21.3 J26.19
VREF2_CON: J22.3 J26.15 U9.H37(LA32_P)
N16986163: R85.1 R91.1 U6.3(W#/SIO2)
N16986165: R87.1 R90.2 U6.7(RESET#/SIO3)
N16986190: C80.1 R92.2 U6.5(SI/SIO0)
N16986210: R89.2 U6.2(S0/SIO1)
N16986259: R80.1 SW5.1 SW5.3
N16986267: C76.1 R77.2 R80.2
N16986368: R78.2 U3.E12(PT76A/MCLK/PCLKT0_0)
N16986967: D18.1(CATHODE) Q1.3(COLLECTOR)
N16986992: D18.2(ANODE) R81.1
N17075797: D28.3(K) F1.1 J39.1(+5V)
N17075854: J40.2 L14.1 R152.2
N17075864: C149.2 R159.1
N17075866: C148.1 C149.1 U15.19(VC2)
N17075880: R155.2 R160.1 U15.18(FB2)
N17075896: J41.1 L15.1 R153.1
N17075942: C143.2 D32.1 L15.2 U15.11(SW2)
N17076139: R158.1 U15.22(RT/SYNC)
N17076167: C143.1 D30.1 U15.12(BOOST2)
N17076187: C145.1 U15.17(TRACK/SS2)
N17076206: R154.2 R156.1 U15.1(FB1)
N17076208: C142.1 D31.1 L14.2 U15.8(SW1)
N17076267: C146.1 C147.1 U15.24(VC1)
N17076279: C146.2 R157.1
N17076283: C142.2 D29.1 U15.7(BOOST1)
N17076342: C144.2 U15.2(TRACK/SS1)
N17078978: J42.2 L16.1 R162.2
N17078984: C157.2 D36.1 L17.2 U16.11(SW2)
N17078989: C164.2 R164.2 R169.1 U16.1(FB1)
N17079013: C167.1 R165.2 R170.1 U16.18(FB2)
N17079015: C157.1 D34.1 U16.12(BOOST2)
N17079060: C160.1 C161.1 U16.24(VC1)
N17079075: C160.2 R166.1
N17079092: C163.2 R168.1
N17079096: C156.2 D33.1 U16.7(BOOST1)
N17079109: C156.1 D35.1 L16.2 U16.8(SW1)
N17079126: C162.1 C163.1 U16.19(VC2)
N17079253: C158.2 U16.2(TRACK/SS1)
N17079439: R167.1 U16.22(RT/SYNC)
N17079459: C159.1 U16.17(TRACK/SS2)
N17079480: J43.1 L17.1 R163.1
N17096100: FB6.1 J38.2 R138.2
N17103877: J28.1 J44.2 R127.1
N17104181: J31.1 J33.2 R130.1
N17168384: J21.2 U3.N13(ADC_REFP0)
N17168405: J22.2 U3.P14(ADC_REFP1)
N17171321: J25.3 R97.1
N17171375: J24.3 J26.3
N17171414: J24.2 R95.1
N17171687: C89.1 C90.1 R98.2 U3.T17(ADC_DP1)
N17197718: D26.2(ANODE) R125.1
N17197719: D27.2(ANODE) R126.1
N17197780: D27.1(CATHODE) Q6.3(COLLECTOR)
N17197781: D26.1(CATHODE) Q5.3(COLLECTOR)
N17247466: C82.1 L12.1 U7.3(EN) U7.4(IN)
N17247856: C84.1 U7.1(FILTER)
N17277478: J26.5 R97.2
N17318347: R140.1 R145.1 U14.3(EN)
N17319505: R142.1 R146.1 U13.4(EN)
N17320608: R143.1 R148.2 U13.2(FB)
N17321965: FB7.1 R149.1
N17323470: FB8.1 R150.1
N17361222: C87.1 C88.1 R95.2 U3.R16(ADC_DP0)
N17419156: FB5.1 J37.2 R137.2
N17419161: C124.1 C125.2 J37.1 R137.1 U3.H12(VCCAUXA)
N17423140: TP13.1(TP) U3.U6(PB16B)
N17442859: R147.1 U13.5(NC)
N17443432: FB4.1 J23.1 R94.1
N17453585: C87.2 C88.2 J25.2 U3.T16(ADC_DN0)
N17456025: C89.2 C90.2 R99.2 U3.U17(ADC_DN1)
N17536721: C105.1 U10.4(SS)
N17536725: C102.1 U10.3(VREG)
N17538930: C100.2 L13.1 U10.6(SW)
N17539158: C101.2 R108.1 R109.2 R110.2 R111.2 R112.2 U10.2(FB)
N17540408: C100.1 U10.7(BOOT)
N17630563: Q6.1(BASE) R133.1
N17630565: Q5.1(BASE) R132.1
N17630568: Q3.1(BASE) R122.1
N17630570: D25.1(CATHODE) Q3.3(COLLECTOR)
N17631144: JP8.1 R110.1
N17631146: JP6.1 R112.1
N17631149: JP7.1 R111.1
N17640390: R151.2 U15.21(~{SHDN})
N17640746: D17.2(ANODE) R79.1
N17693161: Q1.1(BASE) R83.1
N17693448: D20.2(ANODE) R114.1
N17693449: D21.2(ANODE) R115.1
N17693484: D19.2(ANODE) R113.1
N17693556: D23.1(CATHODE) Q2.3(COLLECTOR)
N17693557: D24.1(CATHODE) Q4.3(COLLECTOR)
N17693633: Q4.1(BASE) R124.1
N17693634: Q2.1(BASE) R123.1
N17693688: D23.2(ANODE) R117.1
N17693808: D24.2(ANODE) R118.1
N17693849: D22.1(CATHODE) R121.2
N17694021: D25.2(ANODE) R119.1
N17731721: R161.2 U16.21(~{SHDN})

Not connected (* = marked no-connect by the designer): U3 A18(NC78)* A19(NC77)* B17(NC81)* B18(NC79)* B20(NC75)* C16(NC83)* C18(NC80)* C20(NC76)* D18(NC82)* T2(NC40) T3(NC38) T4(NC33) T5(NC30) U2(NC41) U3(NC39) U4(NC34) U5(NC31) V2(NC42) V4(NC35) V5(NC32) W2(NC43) W4(NC36) Y4(NC37); U9 D34(TRST_L)* H38(LA32_N)*; U15 20(PG2)* 23(PG1)*; U16 20(PG2)* 23(PG1)*

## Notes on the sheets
sheet 9
- Parallel / SPI Config Header
- INITN indicator will light
  if an error occurs during
  configuration programming
- PROGRAMN
- Bank0
- INITN
- DNI
- 3.3v
- DONE indicator will light when
  configuration is successfully
  completed
- Place close to Flash
- 128 Mb SPI Flash
- DONE
- DNI
- J21: 1-2 V1P8_ADC_VREF (Default)
         2-3 J26 connector input
- J22: 1-2 V1P8_ADC_VREF (Default)
         2-3 J26 connector input
- 10K POT
- 1.8v
- J24 ADC_DP0 Select
  1-2 = POT (Default)
  2-3 = J26 Connector
- J25 ADC_DN0 Select
  1-2 = Ground (Default)
  2-3 = J26 Connector
- Keep noisy signals away from ADC circuit
sheet 10
- Bank5
- 1.8v
- Use only below Jumpers:
  No Jumper  1.5V
  Only JP8   1.8V
  Only JP7   2.5V
  Only JP6   3.3V
- Bank3
- Parallel FMC CFG Header
- Bank4
- 1.8v
- 1.8v
- DNI
sheet 11
- 12VIN GOOD
- 3.3v
- Group LEDs together
- 5v
- 2.8v
- 1.0v (CORE)
- 1.8v
- 1.2v
- 1.8v (LDO)
- 1.0v (LDO)
- Flash Voltage Select
  1-2 3.3V (Default)
  2-3 1.8V (Note PMOD2 unavailable)
- RPI / User I/O Voltage Select
  1-2 3.3V (Default)
  2-3 1.8V
sheet 12
- VCC_CORE = 1.0 V
sheet 13
- +1.0 V
  300 mA
- +1.8 V
  500 mA
- Analog VCCA 1.0 V Power
  For DPHY And Serdes
- DPHY, Serdes, ADC And VCCAUX
  Analog 1.8 V Power
- Vout = 0.8*(R143/R148+1) = 1.81 V
- 5.0 V
- 3.3 V
- Right angle
  mount, cable
  to board edge
- K
- +11v to +16v
- 1
- 2
- +3.3 V
  1.35 A
- POWER INPUT
- +5.0 V
  1.1 A
- 1.2v/ms
- 1.2v/ms
- Vout = 0.8*(R154/R156+1) = 5.00 V
- Vout = 0.8*(R155/R160+1) = 3.32 V
- Core Power
- 1.8 V
- 1.0 V
- +1.0 V
  1.35 A
- +1.8 V
  1.1 A
- 1.2v/ms
- 1.2v/ms
- Vout = 0.8*((R164/R169)+1) = 1.01 V
- Vout = 0.8*((R165/R170)+1) = 1.81 V
